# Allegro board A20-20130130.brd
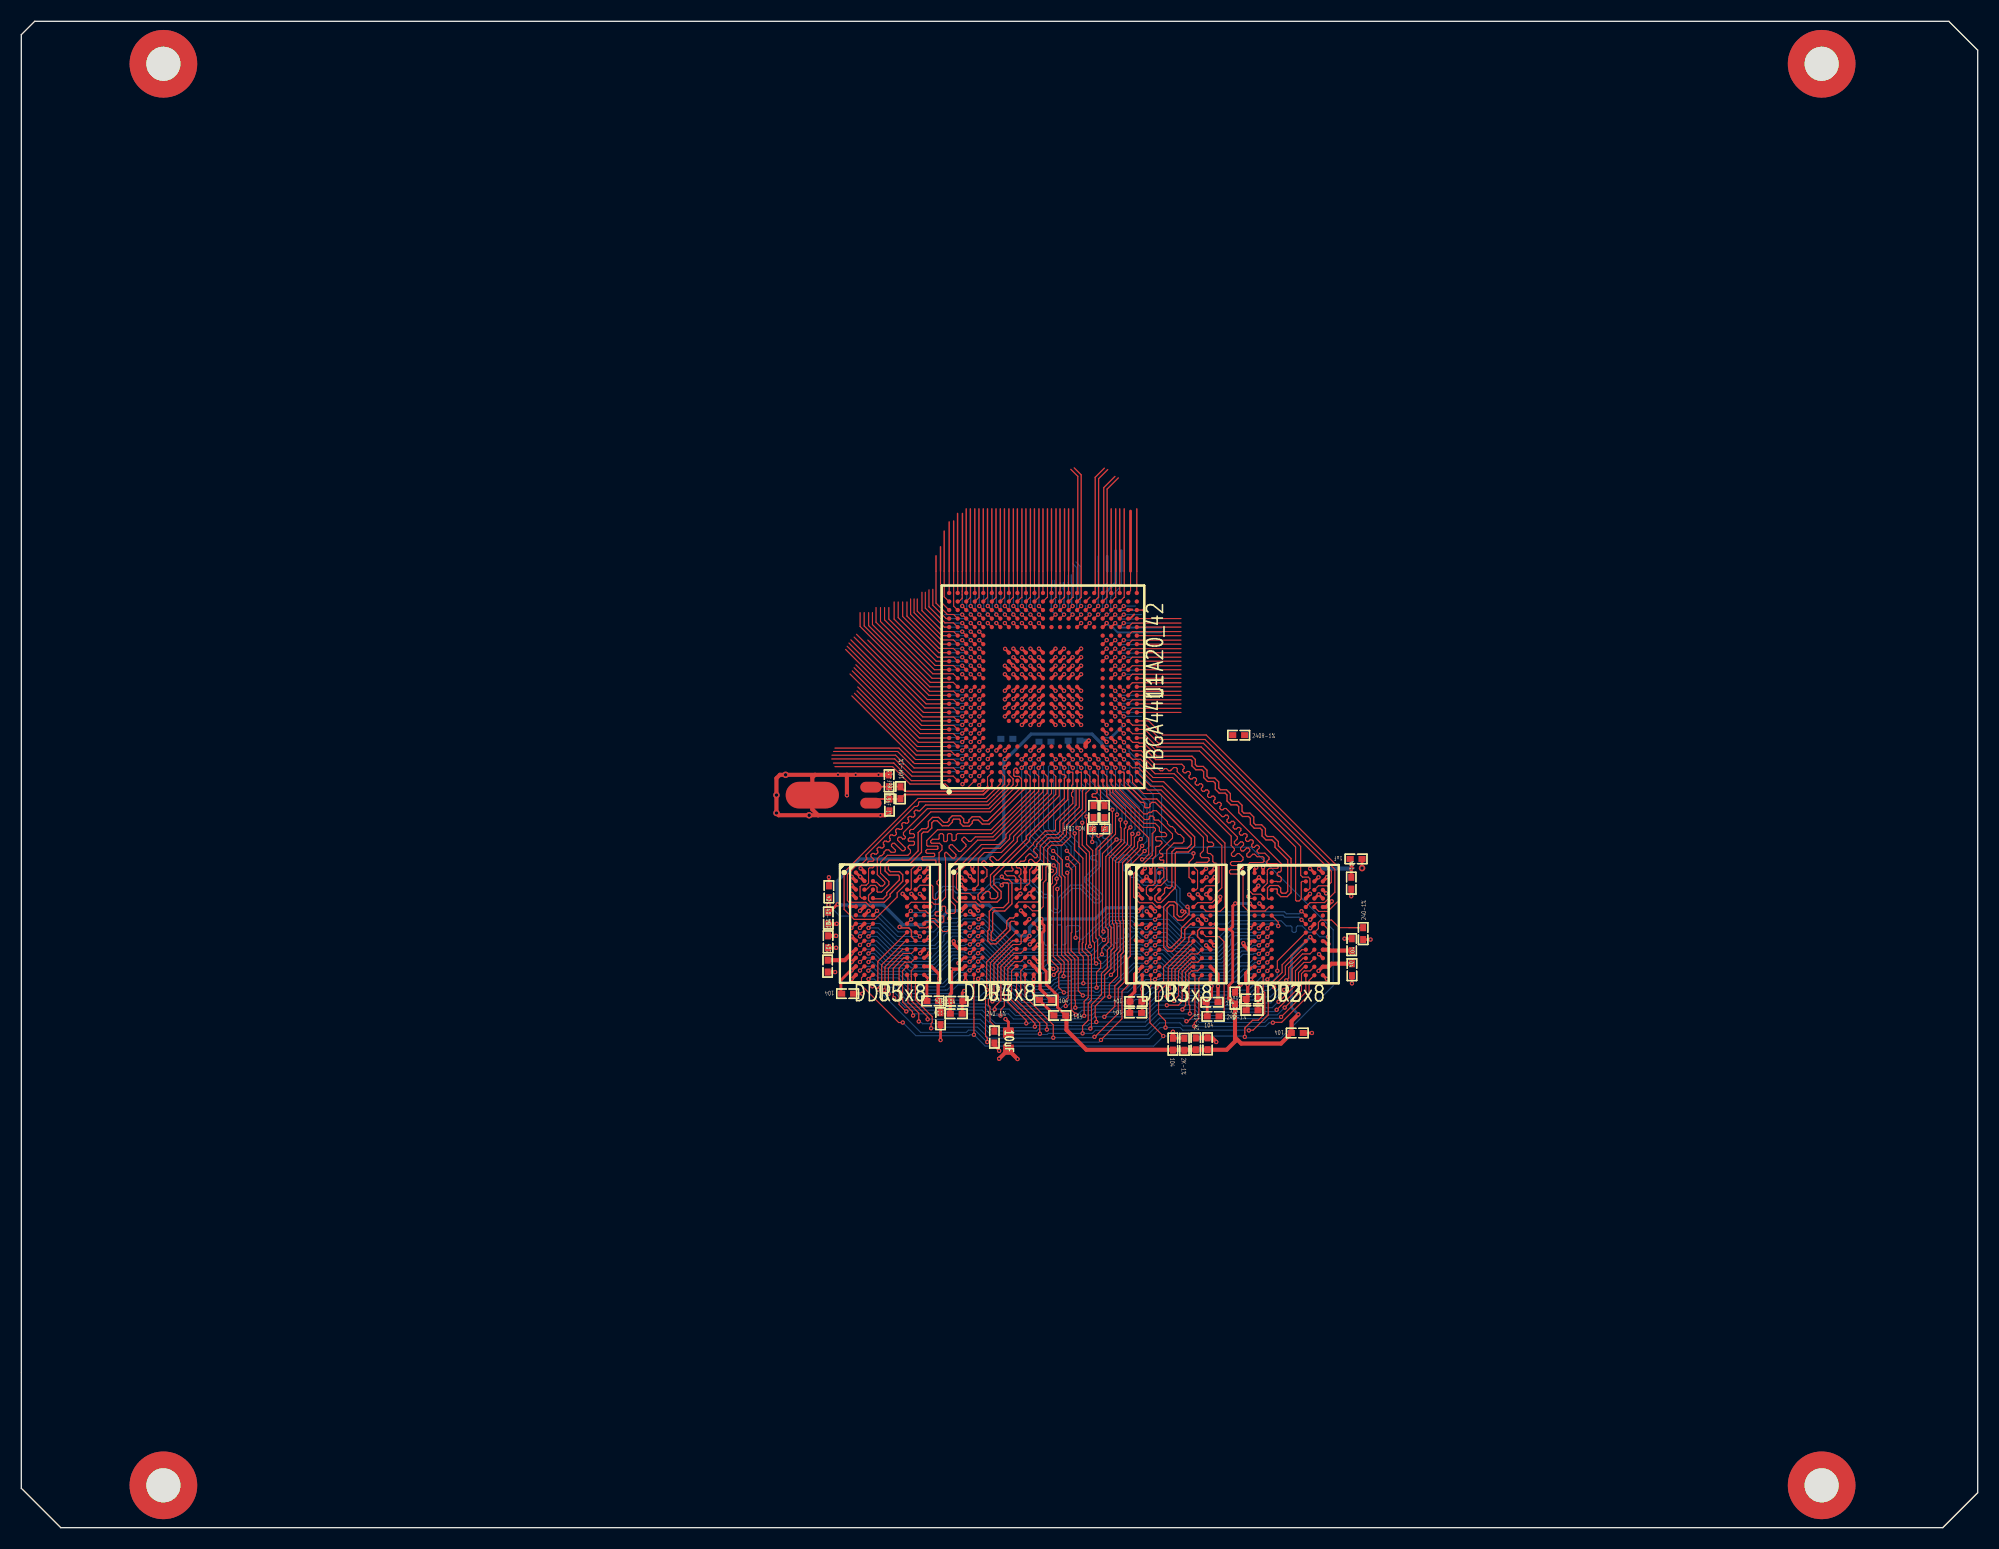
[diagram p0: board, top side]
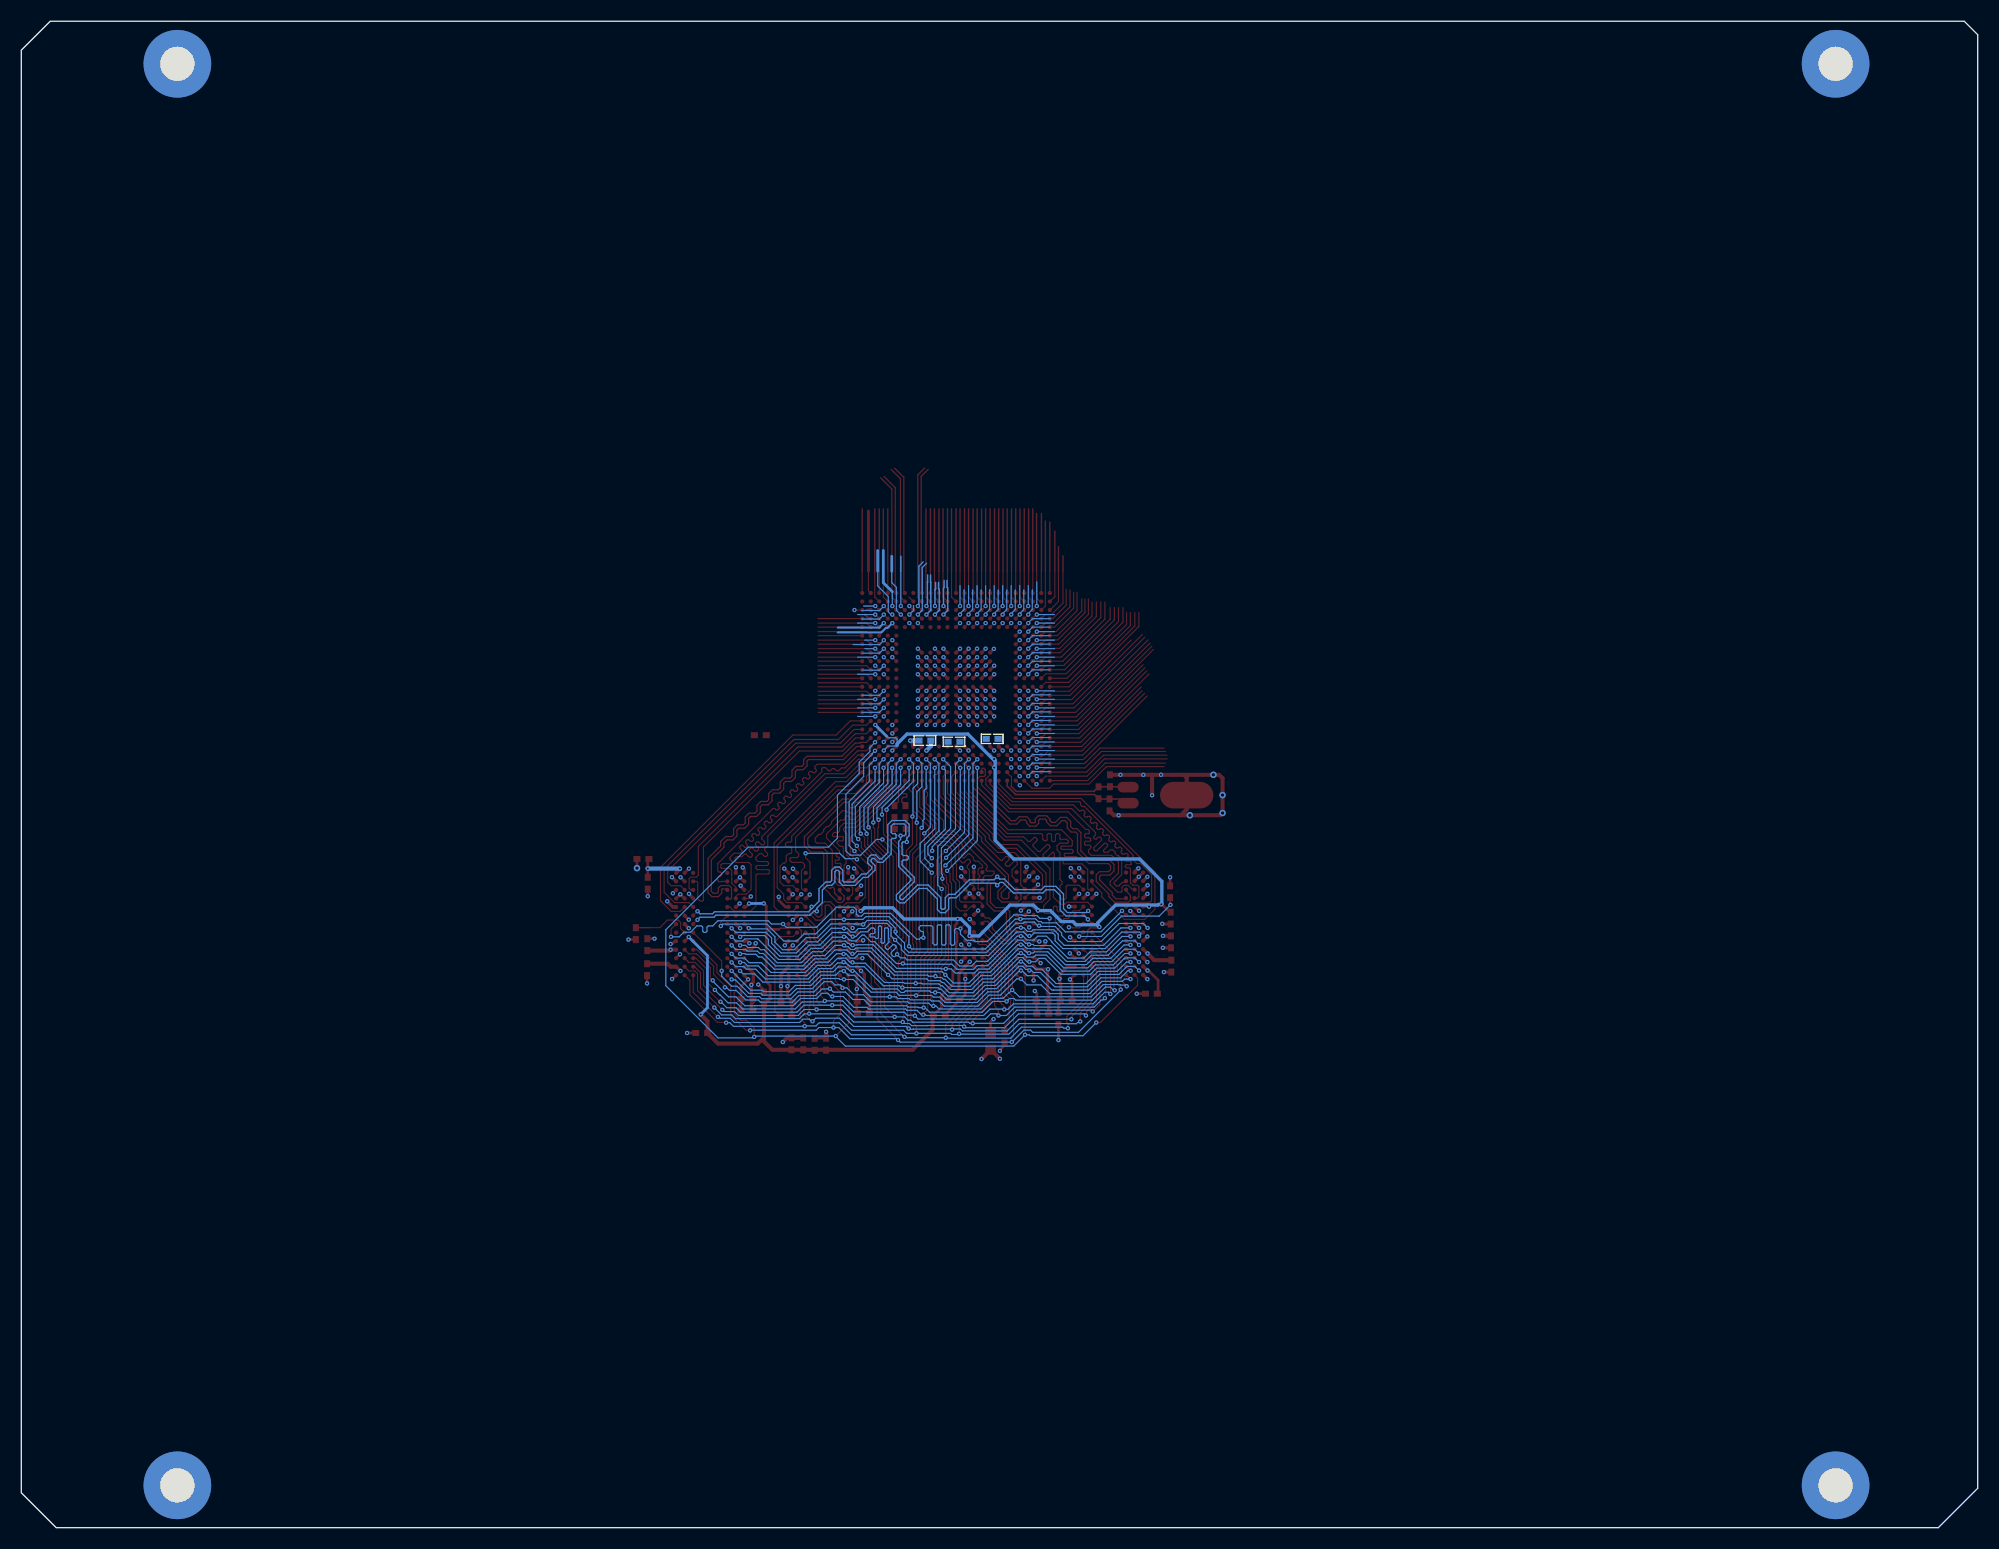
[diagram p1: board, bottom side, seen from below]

Outline 183.55 x 141.31 mm; copper layers: TOP, GND02, PWR03, BOTTOM. Coordinates in mm from the lower left corner of the outline.
Outline path: 0,140.05 1.26,141.31 180.84,141.31 183.55,138.6 183.55,3.28 180.27,0 3.7,0 0,3.7 0,140.05

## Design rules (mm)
net group ACIN-5V: nets ACIN-5V N16771897
net group ACIN-12V: nets ACIN-12V N16771865
net group AVDD10: nets AVDD10 DVDD10
net group BAT: nets BAT CHSENSE
net group BT-PCM-CLK: nets BT-PCM-CLK N23153219
net group BT-PCM-IN: nets BT-PCM-IN N23153300
net group BT-PCM-OUT: nets BT-PCM-OUT N23153273
net group BT-PCM-SYNC: nets BT-PCM-SYNC N23153244
net group BT-RST-N: nets BT-RST-N N23153193
net group CPUVDD: nets CPUVDD N23099887
net group CSI0-HSYNC: nets CSI0-HSYNC CSI0HSYNC
net group CSI0-IO-2V8: nets CSI0-IO-2V8 CSI0-VCC
net group CSI0-MCLK: nets CSI0-MCLK CSI0CK
net group CSI0-PCLK: nets CSI0-PCLK CSI0PCK
net group CSI0-VSYNC: nets CSI0-VSYNC CSI0VSYNC
net group CSI1-HSYNC: nets CSI1-HSYNC CSI1HSYNC
net group CSI1-IO-2V8: nets CSI1-IO-2V8 CSI1-VCC
net group CSI1-MCLK: nets CSI1-MCLK CSI1CK
net group CSI1-PCLK: nets CSI1-PCLK CSI1PCK
net group CSI1-VSYNC: nets CSI1-VSYNC CSI1VSYNC
net group CVBS: nets CVBS TV-CVBS
net group DP2: nets HPL HPR
net group DRAM-1V5: nets DRAM-1V5 N17835604
net group DSCK: nets DSCK SCK
net group DSCK-N: nets DSCK-N SCK-N
net group ERXCLK: nets ERXCLK RXCLK
net group ERXDV: nets ERXDV RXCTL-AD2
net group ESRXM: nets ESRXM N19311986
net group ESRXP: nets ESRXP N19311988
net group ESTXM: nets ESTXM N19311984
net group ESTXP: nets ESTXP N19311982
net group ETXD0: nets ETXD0 TXD0
net group ETXD1: nets ETXD1 TXD1
net group ETXD2: nets ETXD2 TXD2
net group ETXD3: nets ETXD3 TXD3
net group ETXEN: nets ETXEN TXCTL
net group HTX0: nets HTX0N HTX0P
net group HTX1: nets HTX1N HTX1P
net group HTX2: nets HTX2N HTX2P
net group HTXC: nets HTXCN HTXCP
net group IPSOUT: nets IPSOUT N251740
net group LCD0-PWR: nets LCD0-PWR N21047947
net group LED1-AD1: nets LED1-AD1 N22919221
net group LINEINL: nets LINEINL N16783683
net group LINEINR: nets LINEINR N16783681
net group MDI0: nets MDI0+ MDI0-
net group MDI1: nets MDI1+ MDI1-
net group MDI2: nets MDI2+ MDI2-
net group MDI3: nets MDI3+ MDI3-
net group MIC1OUT: nets MIC1OUTN MIC1OUTP
net group N16771869: nets N16771869 N16771893
net group N18122997: nets N18122997 N18122999
net group N18123031: nets N18123031 N18123039
net group N167719710: nets N167719710 N167719711
net group PI15: nets N23269636 PI15
net group QS0-CLK: nets SDQS0 SDQSB0
net group QS1-CLK: nets SDQS1 SDQSB1
net group QS2-CLK: nets SDQS2 SDQSB2
net group QS3-CLK: nets SDQS3 SDQSB3
net group RESET-N: nets N23093396 RESET-N
net group TP-S1: nets TP-S1 X1
net group TP-S2: nets TP-S2 X2
net group TP-S3: nets TP-S3 Y1
net group TP-S4: nets TP-S4 Y2
net group TP-WAKEUP: nets N23153370 TP-WAKEUP
net group UART-VCC: nets N18123022 UART-VCC
net group USB0: nets DM0 DP0
net group USB0-IDDET: nets N19190723 USB0-IDDET
net group USB1: nets DM1 DP1
net group USB2: nets DM2 DP2
net group A-GND: nets A-GND AVCC LRADC0 N2504410 N18051529 N18051532 N18051570 N18051574 N18051579 N18051588 N18051600 VRA1 VRA2 VRP
net group CLK125: nets CLK125 EGCLKIN N23153042
net group DLLVDD: nets DLLVDD ESVDD1V2 N23100083 ULVDD VDD-SYS
net group DQS0-7: nets SDQ0 SDQ1 SDQ2 SDQ3 SDQ4 SDQ5 SDQ6 SDQ7 SDQM0
net group DQS8-15: nets SDQ8 SDQ9 SDQ10 SDQ11 SDQ12 SDQ13 SDQ14 SDQ15 SDQM1
net group DQS16-23: nets SDQ16 SDQ17 SDQ18 SDQ19 SDQ20 SDQ21 SDQ22 SDQ23 SDQM2
net group DQS24-31: nets SDQ24 SDQ25 SDQ26 SDQ27 SDQ28 SDQ29 SDQ30 SDQ31 SDQM3
net group EGTXCLK: nets EGTXCLK N23153083 TXCLK
net group EMDIO: nets EMDIO EPHY-VDD25 ERXD0 ERXD1 ERXD2 ERXD3 ESVDD2V5 N23100213 RXD0-SELRGV RXD1-TXDLY RXD2-AN0 RXD3-AN1 VCC-2V5 VCC-PA VDD25-TVIN
net group ENSWREG: nets ENSWREG EPHY-AVDD33 INTB LED0-AD0 LED2-RXDLY N22919040 N22919042 N22919172 N22919199 PHYRSTB PMEB
net group EPHY-RST-N: nets EPHY-RST-N MAC-RST N23153045
net group HP-GND: nets HP-GND MICIN1 MICIN2 N19446327 N19448131 N29649340 VMIC
net group HSCL: nets HSCL HSDA N18085423 VCC-5V
net group IN0: nets IN0 N17918911 N17918913 TVIN0
net group IN1: nets IN1 N17918934 N17918936 TVIN1
net group IN2: nets IN2 N17919000 N17919002 TVIN2
net group IN3: nets IN3 N17919029 N17919031 TVIN3
net group IRQ: nets IRQ N31589329 NMI-N
net group PWM0: nets N23096818 N23096833 PWM0 VLED-
net group PWR: nets USB0-DRV USB0-VBUSDET USB1-DRV USB2-DRV USBVBUS UVCC VCC33-TVIN VCC-LCD VLED+
net group USB-ICTRL: nets N23265970 N23267698 N23268906 USB-ICTRL

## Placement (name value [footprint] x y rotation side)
C1  104  [C0402]  111.29 45.39 90 top
C2  104  [C0402]  108.04 45.35 270 top
C3  NC-10pF  [C0402]  101.08 65.54 180 top
C4  1uF  [C0402]  115.47 49.59 180 top
C5  104  [C0402]  111.71 49.29 0 top
C6  104  [C0402]  124.82 54.69 270 top
C7  104  [C0402]  124.84 52.34 90 top
C8  1uF  [C0402]  115.47 48.52 180 top
C9  104  [C0402]  124.77 60.45 90 top
C10  104  [C0402]  104.55 48.28 180 top
C11  104  [C0402]  104.57 49.35 180 top
C12  1uF  [C0402]  125.23 62.73 180 top
C13  104  [C0402]  87.78 49.39 180 top
C14  104  [C0402]  85.52 49.41 0 top
C15  104  [C0402]  96.08 49.48 0 top
C16  1uF  [C0402]  86.24 47.75 90 top
C17  104  [C0402]  75.65 52.67 90 top
C18  104  [C0402]  75.69 54.96 90 top
C19  104  [C0402]  87.71 48.21 180 top
C20  10uF  [CC0603]  92.61 45.64 270 top
C21  1uF  [C0402]  98.77 73.83 180 bottom
C22  104  [C0402]  92.46 74 180 bottom
C23  104  [C0402]  77.52 50.09 180 top
C24  104  [C0402]  96.04 73.72 0 bottom
C25  104  [C0402]  75.71 57.18 90 top
C26  104  [C0402]  97.43 48.04 0 top
C27  104  [C0402]  119.71 46.4 180 top
C28  104  [C0402]  113.87 49.67 270 top
C77  18pF-1%  [C0402]  81.45 67.8 90 top
C85  18pF-1%  [C0402]  81.41 70.06 270 top
NOREF  -  [unnamed]  168.9 137.32 0 top
NOREF#2  -  [unnamed]  13.33 3.97 0 top
NOREF#3  -  [unnamed]  13.33 137.32 0 top
NOREF#4  -  [unnamed]  168.9 3.97 0 top
R1  240R-1%  [R0402]  114.21 74.34 0 top
R2  2K-1%  [R0402]  110.19 45.38 90 top
R3  2K-1%  [R0402]  109.12 45.34 270 top
R4  240-1%  [R0402]  125.89 55.73 90 top
R5  240-1%  [R0402]  111.82 47.96 0 top
R6  240-1%  [R0402]  91.29 46.02 90 top
R7  240-1%  [R0402]  75.77 59.65 270 top
R8  24R  [R0402]  100.59 67.18 270 top
R9  24R  [R0402]  101.62 67.17 270 top
R38  10M-1%  [R0402]  82.48 68.94 90 top
U1  FBGA441-A20_42  [FBGA441C80P19X19]  95.85 78.88 90 top
U2  DDR3x8  [FBGA78P0_8B7_5X11]  118.91 56.62 0 top
U3  DDR3x8  [FBGA78P0_8B7_5X11]  108.36 56.62 0 top
U4  DDR3x8  [FBGA78P0_8B7_5X11]  91.78 56.69 0 top
U5  DDR3x8  [FBGA78P0_8B7_5X11]  81.5 56.65 0 top
X2  32768  [XCOL-SMD]  79.71 68.71 90 top

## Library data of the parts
C1 C2 C5-C7 C9-C11 C13-C15 C17-C19 C22-C28 = CAPACITOR_0: signal model: DEFAULT_CAPACITOR_1.04e+014pF_2_1
C3 C77 C85 = CAPACITOR_0
C4 C8 C12 C16 C21 = CAPACITOR_0: signal model: DEFAULT_CAPACITOR_1e+06pF_2_1
C20 = CAPACITOR_0: signal model: DEFAULT_CAPACITOR_1e+07pF_2_1
R1 R4-R7 R38 = R
R2 R3 = ?_0
R8 R9 = R1 0805: signal model: DEFAULT_RESISTOR_24OHM_2_1
U1 = FBGA441-A20_42
U2-U5 = DDR3x8-FBGA78
X2 = CRYSTAL_XCOL-3: Tolerance: RichardLC

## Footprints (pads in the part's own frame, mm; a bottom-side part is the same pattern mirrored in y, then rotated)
C0402
  rect 0.66x0.559 smd: 1(-0.559,0) 2(0.559,0)
CC0603
  rect 0.95x1.001 smd: 1(-0.8,0) 2(0.8,0)
FBGA78P0_8B7_5X11
  round 0.399 smd: A1(-3.2,4.801) A2(-2.4,4.801) A3(-1.6,4.801) A7(1.6,4.801) A8(2.4,4.801) A9(3.2,4.801) B1(-3.2,4) B2(-2.4,4) B3(-1.6,4) B7(1.6,4) B8(2.4,4) B9(3.2,4) C1(-3.2,3.2) C2(-2.4,3.2) C3(-1.6,3.2) C7(1.6,3.2) C8(2.4,3.2) C9(3.2,3.2) D1(-3.2,2.4) D2(-2.4,2.4) D3(-1.6,2.4) D7(1.6,2.4) D8(2.4,2.4) D9(3.2,2.4) E1(-3.2,1.6) E2(-2.4,1.6) E3(-1.6,1.6) E7(1.6,1.6) E8(2.4,1.6) E9(3.2,1.6) F1(-3.2,0.8) F2(-2.4,0.8) F3(-1.6,0.8) F7(1.6,0.8) F8(2.4,0.8) F9(3.2,0.8) G1(-3.2,0) G2(-2.4,0) G3(-1.6,0) G7(1.6,0) G8(2.4,0) G9(3.2,0) H1(-3.2,-0.8) H2(-2.4,-0.8) H3(-1.6,-0.8) H7(1.6,-0.8) H8(2.4,-0.8) H9(3.2,-0.8) J1(-3.2,-1.6) J2(-2.4,-1.6) J3(-1.6,-1.6) J7(1.6,-1.6) J8(2.4,-1.6) J9(3.2,-1.6) K1(-3.2,-2.4) K2(-2.4,-2.4) K3(-1.6,-2.4) K7(1.6,-2.4) K8(2.4,-2.4) K9(3.2,-2.4) L1(-3.2,-3.2) L2(-2.4,-3.2) L3(-1.6,-3.2) L7(1.6,-3.2) L8(2.4,-3.2) L9(3.2,-3.2) M1(-3.2,-4) M2(-2.4,-4) M3(-1.6,-4) M7(1.6,-4) M8(2.4,-4) M9(3.2,-4) N1(-3.2,-4.801) N2(-2.4,-4.801) N3(-1.6,-4.801) N7(1.6,-4.801) N8(2.4,-4.801) N9(3.2,-4.801)
FBGA441C80P19X19
  round 0.399 smd: A1(-8.801,8.801) A2(-8.001,8.801) A3(-7.201,8.801) A4(-6.401,8.801) A5(-5.601,8.801) A6(-4.801,8.801) A7(-4,8.801) A8(-3.2,8.801) A9(-2.4,8.801) A10(-1.6,8.801) A11(-0.8,8.801) A12(0,8.801) A13(0.8,8.801) A14(1.6,8.801) A15(2.4,8.801) A16(3.2,8.801) A17(4,8.801) A18(4.801,8.801) A19(5.601,8.801) A20(6.401,8.801) A21(7.201,8.801) A22(8.001,8.801) A23(8.801,8.801) AA1(-8.801,-7.201) AA2(-8.001,-7.201) AA3(-7.201,-7.201) AA4(-6.401,-7.201) AA5(-5.601,-7.201) AA6(-4.801,-7.201) AA7(-4,-7.201) AA8(-3.2,-7.201) AA9(-2.4,-7.201) AA10(-1.6,-7.201) AA11(-0.8,-7.201) AA12(0,-7.201) AA13(0.8,-7.201) AA14(1.6,-7.201) AA15(2.4,-7.201) AA16(3.2,-7.201) AA17(4,-7.201) AA18(4.801,-7.201) AA19(5.601,-7.201) AA20(6.401,-7.201) AA21(7.201,-7.201) AA22(8.001,-7.201) AA23(8.801,-7.201) AB1(-8.801,-8.001) AB2(-8.001,-8.001) AB3(-7.201,-8.001) AB4(-6.401,-8.001) AB5(-5.601,-8.001) AB6(-4.801,-8.001) AB7(-4,-8.001) AB8(-3.2,-8.001) AB9(-2.4,-8.001) AB10(-1.6,-8.001) AB11(-0.8,-8.001) AB12(0,-8.001) AB13(0.8,-8.001) AB14(1.6,-8.001) AB15(2.4,-8.001) AB16(3.2,-8.001) AB17(4,-8.001) AB18(4.801,-8.001) AB19(5.601,-8.001) AB20(6.401,-8.001) AB21(7.201,-8.001) AB22(8.001,-8.001) AB23(8.801,-8.001) AC1(-8.801,-8.801) AC2(-8.001,-8.801) AC3(-7.201,-8.801) AC4(-6.401,-8.801) AC5(-5.601,-8.801) AC6(-4.801,-8.801) AC7(-4,-8.801) AC8(-3.2,-8.801) AC9(-2.4,-8.801) AC10(-1.6,-8.801) AC11(-0.8,-8.801) AC12(0,-8.801) AC13(0.8,-8.801) AC14(1.6,-8.801) AC15(2.4,-8.801) AC16(3.2,-8.801) AC17(4,-8.801) AC18(4.801,-8.801) AC19(5.601,-8.801) AC20(6.401,-8.801) AC21(7.201,-8.801) AC22(8.001,-8.801) AC23(8.801,-8.801) B1(-8.801,8.001) B2(-8.001,8.001) B3(-7.201,8.001) B4(-6.401,8.001) B5(-5.601,8.001) B6(-4.801,8.001) B7(-4,8.001) B8(-3.2,8.001) B9(-2.4,8.001) B10(-1.6,8.001) B11(-0.8,8.001) B12(0,8.001) B13(0.8,8.001) B14(1.6,8.001) B15(2.4,8.001) B16(3.2,8.001) B17(4,8.001) B18(4.801,8.001) B19(5.601,8.001) B20(6.401,8.001) B21(7.201,8.001) B22(8.001,8.001) B23(8.801,8.001) C1(-8.801,7.201) C2(-8.001,7.201) C3(-7.201,7.201) C4(-6.401,7.201) C5(-5.601,7.201) C6(-4.801,7.201) C7(-4,7.201) C8(-3.2,7.201) C9(-2.4,7.201) C10(-1.6,7.201) C11(-0.8,7.201) C12(0,7.201) C13(0.8,7.201) C14(1.6,7.201) C15(2.4,7.201) C16(3.2,7.201) C17(4,7.201) C18(4.801,7.201) C19(5.601,7.201) C20(6.401,7.201) C21(7.201,7.201) C22(8.001,7.201) C23(8.801,7.201) D1(-8.801,6.401) D2(-8.001,6.401) D3(-7.201,6.401) D4(-6.401,6.401) D5(-5.601,6.401) D6(-4.801,6.401) D7(-4,6.401) D8(-3.2,6.401) D9(-2.4,6.401) D10(-1.6,6.401) D11(-0.8,6.401) D12(0,6.401) D13(0.8,6.401) D14(1.6,6.401) D15(2.4,6.401) D16(3.2,6.401) D17(4,6.401) D18(4.801,6.401) D19(5.601,6.401) D20(6.401,6.401) D21(7.201,6.401) D22(8.001,6.401) D23(8.801,6.401) E1(-8.801,5.601) E2(-8.001,5.601) E3(-7.201,5.601) E4(-6.401,5.601) E5(-5.601,5.601) E6(-4.801,5.601) E7(-4,5.601) E8(-3.2,5.601) E9(-2.4,5.601) E10(-1.6,5.601) E11(-0.8,5.601) E12(0,5.601) E13(0.8,5.601) E14(1.6,5.601) E15(2.4,5.601) E16(3.2,5.601) E17(4,5.601) E18(4.801,5.601) E19(5.601,5.601) E20(6.401,5.601) E21(7.201,5.601) E22(8.001,5.601) E23(8.801,5.601) F1(-8.801,4.801) F2(-8.001,4.801) F3(-7.201,4.801) F4(-6.401,4.801) F5(-5.601,4.801) F19(5.601,4.801) F20(6.401,4.801) F21(7.201,4.801) F22(8.001,4.801) F23(8.801,4.801) G1(-8.801,4) G2(-8.001,4) G3(-7.201,4) G4(-6.401,4) G5(-5.601,4) G19(5.601,4) G20(6.401,4) G21(7.201,4) G22(8.001,4) G23(8.801,4) H1(-8.801,3.2) H2(-8.001,3.2) H3(-7.201,3.2) H4(-6.401,3.2) H5(-5.601,3.2) H8(-3.2,3.2) H9(-2.4,3.2) H10(-1.6,3.2) H11(-0.8,3.2) H12(0,3.2) H13(0.8,3.2) H14(1.6,3.2) H15(2.4,3.2) H16(3.2,3.2) H19(5.601,3.2) H20(6.401,3.2) H21(7.201,3.2) H22(8.001,3.2) H23(8.801,3.2) J1(-8.801,2.4) J2(-8.001,2.4) J3(-7.201,2.4) J4(-6.401,2.4) J5(-5.601,2.4) J8(-3.2,2.4) J9(-2.4,2.4) J10(-1.6,2.4) J11(-0.8,2.4) J12(0,2.4) J13(0.8,2.4) J14(1.6,2.4) J15(2.4,2.4) J16(3.2,2.4) J19(5.601,2.4) J20(6.401,2.4) J21(7.201,2.4) J22(8.001,2.4) J23(8.801,2.4) K1(-8.801,1.6) K2(-8.001,1.6) K3(-7.201,1.6) K4(-6.401,1.6) K5(-5.601,1.6) K8(-3.2,1.6) K9(-2.4,1.6) K10(-1.6,1.6) K11(-0.8,1.6) K12(0,1.6) K13(0.8,1.6) K14(1.6,1.6) K15(2.4,1.6) K16(3.2,1.6) K19(5.601,1.6) K20(6.401,1.6) K21(7.201,1.6) K22(8.001,1.6) K23(8.801,1.6) L1(-8.801,0.8) L2(-8.001,0.8) L3(-7.201,0.8) L4(-6.401,0.8) L5(-5.601,0.8) L8(-3.2,0.8) L9(-2.4,0.8) L10(-1.6,0.8) L11(-0.8,0.8) L12(0,0.8) L13(0.8,0.8) L14(1.6,0.8) L15(2.4,0.8) L16(3.2,0.8) L19(5.601,0.8) L20(6.401,0.8) L21(7.201,0.8) L22(8.001,0.8) L23(8.801,0.8) M1(-8.801,0) M2(-8.001,0) M3(-7.201,0) M4(-6.401,0) M5(-5.601,0) M8(-3.2,0) M9(-2.4,0) M10(-1.6,0) M11(-0.8,0) M12(0,0) M13(0.8,0) M14(1.6,0) M15(2.4,0) M16(3.2,0) M19(5.601,0) M20(6.401,0) M21(7.201,0) M22(8.001,0) M23(8.801,0) N1(-8.801,-0.8) N2(-8.001,-0.8) N3(-7.201,-0.8) N4(-6.401,-0.8) N5(-5.601,-0.8) N8(-3.2,-0.8) N9(-2.4,-0.8) N10(-1.6,-0.8) N11(-0.8,-0.8) N12(0,-0.8) N13(0.8,-0.8) N14(1.6,-0.8) N15(2.4,-0.8) N16(3.2,-0.8) N19(5.601,-0.8) N20(6.401,-0.8) N21(7.201,-0.8) N22(8.001,-0.8) N23(8.801,-0.8) P1(-8.801,-1.6) P2(-8.001,-1.6) P3(-7.201,-1.6) P4(-6.401,-1.6) P5(-5.601,-1.6) P8(-3.2,-1.6) P9(-2.4,-1.6) P10(-1.6,-1.6) P11(-0.8,-1.6) P12(0,-1.6) P13(0.8,-1.6) P14(1.6,-1.6) P15(2.4,-1.6) P16(3.2,-1.6) P19(5.601,-1.6) P20(6.401,-1.6) P21(7.201,-1.6) P22(8.001,-1.6) P23(8.801,-1.6) R1(-8.801,-2.4) R2(-8.001,-2.4) R3(-7.201,-2.4) R4(-6.401,-2.4) R5(-5.601,-2.4) R8(-3.2,-2.4) R9(-2.4,-2.4) R10(-1.6,-2.4) R11(-0.8,-2.4) R12(0,-2.4) R13(0.8,-2.4) R14(1.6,-2.4) R15(2.4,-2.4) R16(3.2,-2.4) R19(5.601,-2.4) R20(6.401,-2.4) R21(7.201,-2.4) R22(8.001,-2.4) R23(8.801,-2.4) T1(-8.801,-3.2) T2(-8.001,-3.2) T3(-7.201,-3.2) T4(-6.401,-3.2) T5(-5.601,-3.2) T8(-3.2,-3.2) T9(-2.4,-3.2) T10(-1.6,-3.2) T11(-0.8,-3.2) T12(0,-3.2) T13(0.8,-3.2) T14(1.6,-3.2) T15(2.4,-3.2) T16(3.2,-3.2) T19(5.601,-3.2) T20(6.401,-3.2) T21(7.201,-3.2) T22(8.001,-3.2) T23(8.801,-3.2) U1(-8.801,-4) U2(-8.001,-4) U3(-7.201,-4) U4(-6.401,-4) U5(-5.601,-4) U19(5.601,-4) U20(6.401,-4) U21(7.201,-4) U22(8.001,-4) U23(8.801,-4) V1(-8.801,-4.801) V2(-8.001,-4.801) V3(-7.201,-4.801) V4(-6.401,-4.801) V5(-5.601,-4.801) V19(5.601,-4.801) V20(6.401,-4.801) V21(7.201,-4.801) V22(8.001,-4.801) V23(8.801,-4.801) W1(-8.801,-5.601) W2(-8.001,-5.601) W3(-7.201,-5.601) W4(-6.401,-5.601) W5(-5.601,-5.601) W6(-4.801,-5.601) W7(-4,-5.601) W8(-3.2,-5.601) W9(-2.4,-5.601) W10(-1.6,-5.601) W11(-0.8,-5.601) W12(0,-5.601) W13(0.8,-5.601) W14(1.6,-5.601) W15(2.4,-5.601) W16(3.2,-5.601) W17(4,-5.601) W18(4.801,-5.601) W19(5.601,-5.601) W20(6.401,-5.601) W21(7.201,-5.601) W22(8.001,-5.601) W23(8.801,-5.601) Y1(-8.801,-6.401) Y2(-8.001,-6.401) Y3(-7.201,-6.401) Y4(-6.401,-6.401) Y5(-5.601,-6.401) Y6(-4.801,-6.401) Y7(-4,-6.401) Y8(-3.2,-6.401) Y9(-2.4,-6.401) Y10(-1.6,-6.401) Y11(-0.8,-6.401) Y12(0,-6.401) Y13(0.8,-6.401) Y14(1.6,-6.401) Y15(2.4,-6.401) Y16(3.2,-6.401) Y17(4,-6.401) Y18(4.801,-6.401) Y19(5.601,-6.401) Y20(6.401,-6.401) Y21(7.201,-6.401) Y22(8.001,-6.401) Y23(8.801,-6.401)
R0402
  rect 0.66x0.559 smd: 1(-0.559,0) 2(0.559,0)
unnamed
  round 6.35 hole 3.2: (0,0)
XCOL-SMD
  oval 1.001x1.999 smd: 1(-0.749,0) 2(0.749,0)
  oval 2.499x4.999 smd: 3(0,5.499)

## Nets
AGND: C2.1 C4.1 C5.1 C6.1 C7.1 C8.1 C9.1 C10.1 C11.1 C12.1 C13.1 C14.1 C15.1 C16.1 C17.1 C18.1 C19.1 C20.1 C21.1 C22.1 C23.1 C24.1 C25.1 C26.1 C27.1 C28.1 C77.1 C85.1 R1.2 R3.1 R4.1 R5.1 R6.1 R7.1 U1.AA18(GND46) U1.G3(GND0) U1.G4(GND1) U1.H16(TEST) U1.J5(GND2) U1.J11(GND13) U1.K5(GND3) U1.K11(GND14) U1.K12(GND15) U1.K13(GND16) U1.K14(GND35) U1.L10(GND17) U1.L11(GND18) U1.L12(GND19) U1.L13(GND36) U1.L14(GND37) U1.M9(GND10) U1.M10(GND20) U1.M11(GND21) U1.M12(GND22) U1.M13(GND23) U1.M14(GND38) U1.N5(GND4) U1.N10(GND11) U1.N11(GND24) U1.N12(GND25) U1.N13(GND39) U1.N14(GND40) U1.P5(GND5) U1.P10(GND12) U1.P11(GND26) U1.P12(GND27) U1.P13(GND43) U1.P14(GND42) U1.P15(PLLGND) U1.R11(GND28) U1.R12(GND29) U1.R13(GND41) U1.R14(NC1) U1.R16(NC0) U1.T11(GND30) U1.T12(GND31) U1.U5(GND6) U1.V5(GND7) U1.V19(HPGND) U1.W9(GND32) U1.W10(GND33) U1.W11(GND34) U1.W18(GND45) U1.Y7(GND8) U1.Y8(GND9) U1.Y18(GND44) U2.A1(VSS1) U2.A8(VSS2) U2.B1(VSS3) U2.B2(VSSQ1) U2.B8(VSSQ2) U2.C9(VSSQ3) U2.D1(VSSQ4) U2.D8(VSS4) U2.D9(VSSQ5) U2.F2(VSS5) U2.F8(VSS6) U2.J1(VSS7) U2.J9(VSS8) U2.L1(VSS9) U2.L9(VSS10) U2.N1(VSS11) U2.N9(VSS12) U3.A1(VSS1) U3.A8(VSS2) U3.B1(VSS3) U3.B2(VSSQ1) U3.B8(VSSQ2) U3.C9(VSSQ3) U3.D1(VSSQ4) U3.D8(VSS4) U3.D9(VSSQ5) U3.F2(VSS5) U3.F8(VSS6) U3.J1(VSS7) U3.J9(VSS8) U3.L1(VSS9) U3.L9(VSS10) U3.N1(VSS11) U3.N9(VSS12) U4.A1(VSS1) U4.A8(VSS2) U4.B1(VSS3) U4.B2(VSSQ1) U4.B8(VSSQ2) U4.C9(VSSQ3) U4.D1(VSSQ4) U4.D8(VSS4) U4.D9(VSSQ5) U4.F2(VSS5) U4.F8(VSS6) U4.J1(VSS7) U4.J9(VSS8) U4.L1(VSS9) U4.L9(VSS10) U4.N1(VSS11) U4.N9(VSS12) U5.A1(VSS1) U5.A8(VSS2) U5.B1(VSS3) U5.B2(VSSQ1) U5.B8(VSSQ2) U5.C9(VSSQ3) U5.D1(VSSQ4) U5.D8(VSS4) U5.D9(VSSQ5) U5.F2(VSS5) U5.F8(VSS6) U5.J1(VSS7) U5.J9(VSS8) U5.L1(VSS9) U5.L9(VSS10) U5.N1(VSS11) U5.N9(VSS12) X2.3(SHIELD)
AVCC: U1.T19(AVCC)
VCC33-TVIN: U1.W16(VCC33-TVIN)
VCC-PA: U1.H10(VCC0-PA) U1.J10(VCC1-PA)
VDD25-TVIN: U1.W17(VDD25-TVIN)
VDD-SYS: U1.J15(VDD0-SYS) U1.J16(VDD1-SYS) U1.K9(VDD2-SYS) U1.K10(VDD3-SYS) U1.K15(VDD4-SYS) U1.L8(VDD5-SYS) U1.L9(VDD6-SYS) U1.R9(VDD7-SYS) U1.R10(VDD8-SYS) U1.T8(VDD9-SYS)
A-GND: U1.U19(AGND)
BT-GPIO0: U1.E14(HSCL/UART7_TX/PS2_SCK0/PI20)
BT-GPIO1: U1.E13(HSDA/UART7_RX/PS2_SDA0/PI21)
BT-PCM-CLK: U1.A12(I2S_BCLK/AC97_BCLK/PB6)
BT-PCM-IN: U1.C9(I2S_DI/AC97_DI/SPDIF_DI/PB12)
BT-PCM-OUT: U1.A11(I2S_DO0/AC97_DO/PB8)
BT-PCM-SYNC: U1.B12(I2S_LRCK/AC97_SYNC/PB7)
BT-RST-N: U1.B13(I2S_MCLK/AC97_MCLK/PB5)
BT-UART-CTS: U1.E16(EINT29/SPI1_CLK/UART2_CTS/PI17)
BT-UART-RTS: U1.E17(EINT28/SPI1_CS0/UART2_RTS/PI16)
BT-UART-RX: U1.D14(EINT31/SPI1_MISO/UART2_RX/PI19)
BT-UART-TX: U1.E15(EINT30/SPI1_MOSI/UART2_TX/PI18)
CLK32K-IN: C77.2 R38.1 U1.F1(X32KI) X2.1
CLK32K-OUT: C85.2 R38.2 U1.F2(X32KO) X2.2
CP-INT: U1.D16(SPI0_MISO/UART6_RX/CLK_OUT_B/EI)
CP-RST-N: U1.B14(IR0_TX/SPDIF_MCLK/STANBYWFI/PB3)
CPU-REF: C1.1 C2.2 C25.2 C26.2 C27.2 C28.2 R2.1 R3.2 U1.AA8(SVREF3) U1.H3(SVREF0) U1.H4(SVREF1) U1.Y5(SVREF2) U2.E1(VREFDQ) U2.J8(VREFCA) U3.E1(VREFDQ) U3.J8(VREFCA) U4.E1(VREFDQ) U4.J8(VREFCA) U5.E1(VREFDQ) U5.J8(VREFCA)
CPUVDD: U1.H11(VDD0-CPU) U1.H12(VDD1-CPU) U1.H13(VDD2-CPU) U1.H14(VDD3-CPU) U1.J12(VDD4-CPU) U1.J13(VDD5-CPU)
CSI0-D0: U1.C23(TS0_D0/CSI0_D0/PE4)
CSI0-D1: U1.C22(TS0_D1/CSI0_D1/PE5)
CSI0-D2: U1.B23(TS0_D2/CSI0_D2/PE6)
CSI0-D3: U1.B22(TS0_D3/CSI0_D3/PE7)
CSI0-D4: U1.A23(TS0_D4/CSI0_D4/PE8)
CSI0-D5: U1.A22(TS0_D5/CSI0_D5/PE9)
CSI0-D6: U1.B21(TS0_D6/CSI0_D6/PE10)
CSI0-D7: U1.A21(TS0_D7/CSI0_D7/PE11)
CSI0-HSYNC: U1.D23(TS0_SYNC/CSI0_HSYNC/PE2)
CSI0-MCLK: U1.E22(TS0_ERR/CSI0_MCLK/PE1)
CSI0-PCLK: U1.E23(TS0_CLK/CSI0_PCLK/PE0)
CSI0-PWR: U1.B1(LCD1_D16/ETXD1/KP_IN6/SMC_DET/E)
CSI0-RST-N: U1.A2(LCD1_D13/PS2_SDA1/SMC_RST/EINT1)
CSI0-VCC: U1.F19(VCC-PE)
CSI0-VSYNC: U1.D22(TS0_DVLD/CSI0_VSYNC/PE3)
CSI1-D0: U1.D20(TS1_D0/CSI1_D0/SDC1_D2/CSI0_D8/)
CSI1-D1: U1.C21(TS1_D1/CSI1_D1/SDC1_D3/CSI0_D9/)
CSI1-D2: U1.E19(TS1_D2/CSI1_D2/UART3_TX/CSI0_D1)
CSI1-D3: U1.C20(TS1_D3/CSI1_D3/UART3_RX/CSI0_D1)
CSI1-D4: U1.D19(TS1_D4/CSI1_D4/UART3_RTS/CSI0_D)
CSI1-D5: U1.C19(TS1_D5/CSI1_D5/UART3_CTS/CSI0_D)
CSI1-D6: U1.D18(TS1_D6/CSI1_D6/UART4_TX/CSI0_D1)
CSI1-D7: U1.C18(TS1_D7/CSI1_D7/UART4_RX/CSI0_D1)
CSI1-HSYNC: U1.E20(TS1_SYNC/CSI1_HSYNC/SDC1_D0/PG2)
CSI1-MCLK: U1.E21(TS1_ERR/CSI1_MLCK/SDC1_CLK/PG1)
CSI1-PCLK: U1.F20(TS1_CLK/CSI1_PCLK/SDC1_CMD/PG0)
CSI1-PWR: U1.C1(LCD1_D17/ETXD0/KP_IN7/SMC_VCCEN)
CSI1-RST-N: U1.B2(LCD1_D14/ETXD3/KP_IN4/SMC_VPPEN)
CSI1-VCC: U1.E18(VCC-PG)
CSI1-VSYNC: U1.D21(TS1_DVLD/CSI1_VSYNC/SDC1_D1/PG3)
CVBS: U1.AB17(TVOUT3)
DLLVDD: U1.M8(VDD0-DLL) U1.N9(VDD1-DLL) U1.P9(VDD2-DLL)
DM0: U1.N20(DM0)
DM1: U1.P20(DM1)
DM2: U1.R20(DM2)
DP0: U1.N21(DP0)
DP1: U1.P21(DP1)
DP2: U1.R21(DP2)
DRAM-VCC: C1.2 C4.2 C5.2 C6.2 C7.2 C8.2 C9.2 C10.2 C11.2 C12.2 C13.2 C14.2 C15.2 C16.2 C17.2 C18.2 C19.2 C20.2 C21.2 C22.2 C23.2 C24.2 R2.2 U1.G5(VCC0-DRAM) U1.H5(VCC1-DRAM) U1.L5(VCC2-DRAM) U1.M5(VCC3-DRAM) U1.R5(VCC4-DRAM) U1.T5(VCC5-DRAM) U1.W5(VCC6-DRAM) U1.W6(VCC7-DRAM) U1.W7(VCC8-DRAM) U1.Y6(VCC9-DRAM) U2.A2(VDD1) U2.A9(VDD2) U2.B9(VDDQ1) U2.C1(VDDQ2) U2.D7(VDD3) U2.E2(VDDQ3) U2.E9(VDDQ4) U2.G2(VDD4) U2.G8(VDD5) U2.K1(VDD6) U2.K9(VDD7) U2.M1(VDD8) U2.M9(VDD9) U3.A2(VDD1) U3.A9(VDD2) U3.B9(VDDQ1) U3.C1(VDDQ2) U3.D7(VDD3) U3.E2(VDDQ3) U3.E9(VDDQ4) U3.G2(VDD4) U3.G8(VDD5) U3.K1(VDD6) U3.K9(VDD7) U3.M1(VDD8) U3.M9(VDD9) U4.A2(VDD1) U4.A9(VDD2) U4.B9(VDDQ1) U4.C1(VDDQ2) U4.D7(VDD3) U4.E2(VDDQ3) U4.E9(VDDQ4) U4.G2(VDD4) U4.G8(VDD5) U4.K1(VDD6) U4.K9(VDD7) U4.M1(VDD8) U4.M9(VDD9) U5.A2(VDD1) U5.A9(VDD2) U5.B9(VDDQ1) U5.C1(VDDQ2) U5.D7(VDD3) U5.E2(VDDQ3) U5.E9(VDDQ4) U5.G2(VDD4) U5.G8(VDD5) U5.K1(VDD6) U5.K9(VDD7) U5.M1(VDD8) U5.M9(VDD9)
DSCK: C3.2 R8.2 U2.F7(CK) U3.F7(CK) U4.F7(CK) U5.F7(CK)
DSCK-N: C3.1 R9.2 U2.G7(\\C\K) U3.G7(\\C\K) U4.G7(\\C\K) U5.G7(\\C\K)
EFUSE-VDDQ: U1.T9(VDDQE)
EGCLKIN: U1.D13(ECOL/GCLKIN/CAN_TX/UART1_DCD/I2)
EGTXCLK: U1.E12(ECRS/GTXCK/UART7_RX/UART1_DSR/I)
EMDC: U1.E10(MDC/UART1_RX/PA11)
EMDIO: U1.D11(MDIO/UART6_TX/UART1_RTS/PA12)
EPHY-RST-N: U1.C13(ETXERR/CAN_RX/UART1_RING/I2S1_D)
ERXCLK: U1.D9(RXCK/SPI3_MISO/PA8)
ERXD0: U1.E6(RXD0/SPI1_MISO/UART2_RX/PA3)
ERXD1: U1.D6(RXD1/SPI1_MOSI/UART2_TX/PA2)
ERXD2: U1.E5(RXD2/SPI1_CLK/UART2_CTS/PA1)
ERXD3: U1.D5(RXD3/SPI1_CS0/UART2_RTS/PA0)
ERXDV: U1.D10(ERXDV/GRXCTL/UART1_TX/PA10)
ESREXT: U1.V21(REXT_SATA)
ESRXM: U1.U20(RXM_SATA)
ESRXP: U1.U21(RXP_SATA)
ESTXM: U1.T21(TXM_SATA)
ESTXP: U1.T20(TXP_SATA)
ESVDD1V2: U1.M15(VDD12-0-SATA) U1.M16(VDD12-1-SATA)
ESVDD2V5: U1.N15(VDD25-0-SATA) U1.N16(VDD25-1-SATA)
ETXD0: U1.E8(TXD0/SPI3_MOSI/PA7)
ETXD1: U1.D8(TXD1/SPI3_CLK/PA6)
ETXD2: U1.E7(TXD2/SPI3_CS0/PA5)
ETXD3: U1.D7(TXD3/SPI1_CS1/PA4)
ETXEN: U1.E11(ETXEN/GTXCTL/UART6_RX/UART1_CTS)
FMINL: U1.Y20(FMINL)
FMINR: U1.Y21(FMINR)
GS-INT1: U1.A6(LCD1_D0/UART3_TX/EINT0/CSI1_D0/)
GY-INT1: U1.C2(LCD1_D18/ERXCK/KP_OUT0/SMC_SLK/)
GY-INT2: U1.D1(LCD1_D19/ERXERR/KP_OUT1/SMC_SDA)
HCEC: U1.P23(CEC_HDMI)
HHPD: U1.P22(HPD_HDMI)
HPBP: U1.AC19(HPBP)
HPCOM: U1.AA19(HPCOM) U1.AA20(HPCOMFB)
HPL: U1.Y19(HPOUTL)
HPR: U1.W19(HPOUTR)
HPVCC: U1.AB19(VCC-HP) U1.H8(VCC0) U1.H9(VCC1) U1.H15(VCC2) U1.J8(VCC3) U1.J9(VCC4) U1.J14(VCC5) U1.N19(VCC-PF) U1.W12(VCC0-LVDS) U1.W13(VCC1-LVDS) U1.W14(VCC2-LVDS)
HSCL: U1.R23(SCL_HDMI)
HSDA: U1.R22(SDA_HDMI)
HTX0N: U1.V22(TX0N_HDMI)
HTX0P: U1.V23(TX0P_HDMI)
HTX1N: U1.U22(TX1N_HDMI)
HTX1P: U1.U23(TX1P_HDMI)
HTX2N: U1.T22(TX2N_HDMI)
HTX2P: U1.T23(TX2P_HDMI)
HTXCN: U1.W22(TXCN_HDMI)
HTXCP: U1.W23(TXCP_HDMI)
HVP: U1.T13(VCC-HDMI)
HVREGIO1: U1.T14(VREG1_HDMI)
I2S1-BCLK: U1.D12(ETXCK/UART7_TX/UART1_DTR/I2S1_B)
I2S1-MCLK: U1.E9(ERXERR/SPI3_CS1/I2S1_MCLK/PA9)
IR-RX: U1.A13(IR0_RX/PB4)
JTAG-CK: U1.B10(JTAG_CK0/SPI2_CLK/PB15)
JTAG-DI: U1.B9(JTAG_DI0/SPI2_MISO/PB17)
JTAG-DO: U1.A9(JTAG_DO0/SPI2_MOSI/PB16)
JTAG-MS: U1.A10(JTAG_MS0/SPI2_CS0/PB14)
JTAG-SEL: U1.T10(JTAG_SEL)
LCD0-BL-EN: U1.B4(LCD1_D7/UART5_RX/MS_CLK/EINT7/C)
LCD0-CLK: U1.Y9(LCD0_CLK/SMC_VCCEN/PD24)
LCD0-D0: U1.AB15(LCD0_D0/LVDS0_VP0/PD0)
LCD0-D1: U1.AC15(LCD0_D1/LVDS0_VN0/PD1)
LCD0-D2: U1.AB14(LCD0_D2/LVDS0_VP1/PD2)
LCD0-D3: U1.AC14(LCD0_D3/LVDS0_VN1/PD3)
LCD0-D4: U1.AB13(LCD0_D4/LVDS0_VP2/PD4)
LCD0-D5: U1.AC13(LCD0_D5/LVDS0_VN2/PD5)
LCD0-D6: U1.AB12(LCD0_D6/LVDS0_VPC/PD6)
LCD0-D7: U1.AC12(LCD0_D7/LVDS0_VNC/PD7)
LCD0-D8: U1.AB11(LCD0_D8/LVDS0_VP3/PD8)
LCD0-D9: U1.AC11(LCD0_D9/LVDS0_VN3/PD9)
LCD0-D10: U1.Y15(LCD0_D10/LVDS1_VP0/PD10)
LCD0-D11: U1.AA15(LCD0_D11/LVDS1_VN0/PD11)
LCD0-D12: U1.Y14(LCD0_D12/LVDS1_VP1/PD12)
LCD0-D13: U1.AA14(LCD0_D13/LVDS1_VN1/PD13)
LCD0-D14: U1.Y13(LCD0_D14/LVDS1_VP2/PD14)
LCD0-D15: U1.AA13(LCD0_D15/LVDS1_VN2/PD15)
LCD0-D16: U1.Y12(LCD0_D16/LVDS1_VPC/PD16)
LCD0-D17: U1.AA12(LCD0_D17/LVDS1_VNC/PD17)
LCD0-D18: U1.Y11(LCD0_D18/LVDS1_VP3/PD18)
LCD0-D19: U1.AA11(LCD0_D19/LVDS1_VN3/PD19)
LCD0-D20: U1.Y10(LCD0_D20/CSI1_MCLK/PD20)
LCD0-D21: U1.AA10(LCD0_D21/SMC_VPPEN/PD21)
LCD0-D22: U1.AB10(LCD0_D22/SMC_VPPPP/PD22)
LCD0-D23: U1.AC10(LCD0_D23/SMC_DET/PD23)
LCD0-DE: U1.AA9(LCD0_DE/SMC_RST/PD25)
LCD0-HSYNC: U1.AB9(LCD0_HSYNC/SMC_SLK/PD26)
LCD0-PWR: U1.C4(LCD1_D8/ERXD3/KP_IN0/MS_D0/EINT)
LCD0-SCK: U1.C11(I2S_DO2/PB10)
LCD0-SDA: U1.C10(I2S_DO3/PB11)
LCD0-VSYNC: U1.AC9(LCD0_VSYNC/SMC_SDA/PD27)
LINEINL: U1.AB20(LINEINL)
LINEINR: U1.AB21(LINEINR)
LRADC0: U1.AB23(LRADC0)
LRADC1: U1.AB22(LRADC1)
LS-INT: U1.D2(LCD1_D20/ERXDV/CAN_TX/EINT20/CS)
MIC1OUTN: U1.AC23(PHOUTN)
MIC1OUTP: U1.AC22(PHOUTP)
MICIN1: U1.AC20(MICIN1)
MICIN2: U1.AC21(MICIN2)
NALE: U1.M22(NALE/SPI0_MISO/PC1)
NAND-VCC: U1.H19(VCC0-PC) U1.J19(VCC1-PC)
NCE0-N: U1.K23(NCE0/PC4)
NCE1-N: U1.L22(NCE1/PC3)
NCE2-N: U1.F23(NCE2/PC17)
NCE3-N: U1.F22(NCE3/PC18)
NCLE: U1.L23(NCLE/SPI0_CLK/PC2)
ND0: U1.H23(NDQ0/SDC2_D0/PC8)
ND1: U1.H22(NDQ1/SDC2_D1/PC9)
ND2: U1.G23(NDQ2/SDC2_D2/PC10)
ND3: U1.G22(NDQ3/SDC2_D3/PC11)
ND4: U1.H21(NDQ4/PC12)
ND5: U1.H20(NDQ5/PC13)
ND6: U1.G21(NDQ6/PC14)
ND7: U1.G20(NDQ7/PC15)
NDQS: U1.F21(NDQS/PC24)
NMI-N: U1.F5(NMI#)
NRB0-N: U1.J23(NRB0/SDC2_CMD/PC6)
NRB1-N: U1.J22(NRB1/SDC2_CLK/PC7)
NRE-N: U1.K22(NRE#/PC5)
NWE-N: U1.M23(NWE#/SPI0_MOSI/PC0)
NWP: U1.M21(NWP/PC16)
OSC24MI: U1.N23(X24MI)
OSC24MO: U1.N22(X24MO)
PA-SHDN-N: U1.A1(LCD1_D15/ETXD2/KP_IN5/SMC_VPPPP)
PC19: U1.L21(NCE4/SPI2_CS0/PC19)
PC20: U1.K21(NCE5/SPI2_CLK/PC20)
PC21: U1.J21(NCE6/SPI2_MOSI/PC21)
PC22: U1.J20(NCE7/SPI2_MISO/PC22)
PI10: U1.C17(SPI0_CS0/UART5_TX/EINT22/PI10)
PI11: U1.D17(SPI0_CLK/UART5_RX/EINT23/PI11)
PI12: U1.C16(SPI0_MOSI/UART6_TX/CLK_OUT_A/EI)
PI14: U1.C15(PS2_SCK1/TCLKIN0/EINT26/SPI0_CS)
PI15: U1.D15(PS2_SDA1/TCLKIN1/EINT27/SPI1_CS)
PLLDV: U1.T16(PLLDV)
PLLVP: U1.P16(VCC-PLL)
PLLVREG: U1.R15(PLLVREG)
PWM0: U1.A14(PWM0/PB2)
RESET-N: U1.C14(RESET#)
RTCVDD: U1.K8(VDD-RTC)
SA0: U1.W4(SA0) U2.K3(A0) U3.K3(A0) U4.K3(A0) U5.K3(A0)
SA1: U1.R4(SA1) U2.L7(A1) U3.L7(A1) U4.L7(A1) U5.L7(A1)
SA2: U1.U4(SA2) U2.L3(A2) U3.L3(A2) U4.L3(A2) U5.L3(A2)
SA3: U1.M4(SA3) U2.K2(A3) U3.K2(A3) U4.K2(A3) U5.K2(A3)
SA4: U1.Y4(SA4) U2.L8(A4) U3.L8(A4) U4.L8(A4) U5.L8(A4)
SA5: U1.N4(SA5) U2.L2(A5) U3.L2(A5) U4.L2(A5) U5.L2(A5)
SA6: U1.V4(SA6) U2.M8(A6) U3.M8(A6) U4.M8(A6) U5.M8(A6)
SA7: U1.M3(SA7) U2.M2(A7) U3.M2(A7) U4.M2(A7) U5.M2(A7)
SA8: U1.AA3(SA8) U2.N8(A8) U3.N8(A8) U4.N8(A8) U5.N8(A8)
SA9: U1.P4(SA9) U2.M3(A9) U3.M3(A9) U4.M3(A9) U5.M3(A9)
SA10: U1.L3(SA10) U2.H7(A10/AP) U3.H7(A10/AP) U4.H7(A10/AP) U5.H7(A10/AP)
SA11: U1.W3(SA11) U2.M7(A11) U3.M7(A11) U4.M7(A11) U5.M7(A11)
SA12: U1.P3(SA12) U2.K7(A12/BC#) U3.K7(A12/BC#) U4.K7(A12/BC#) U5.K7(A12/BC#)
SA13: U1.Y3(SA13) U2.N3(A13) U3.N3(A13) U4.N3(A13) U5.N3(A13)
SA14: U1.R3(SA14) U2.N7(A14) U3.N7(A14) U4.N7(A14) U5.N7(A14)
SA15: U1.AA4(SA15) U2.J7(A15) U3.J7(A15) U4.J7(A15) U5.J7(A15)
SBA0: U1.K3(SBA0) U2.J2(BA0) U3.J2(BA0) U4.J2(BA0) U5.J2(BA0)
SBA1: U1.L4(SBA1) U2.K8(BA1) U3.K8(BA1) U4.K8(BA1) U5.K8(BA1)
SBA2: U1.K4(SBA2) U2.J3(BA2) U3.J3(BA2) U4.J3(BA2) U5.J3(BA2)
SCAS: U1.U3(SCAS) U2.G3(\\C\A\S) U3.G3(\\C\A\S) U4.G3(\\C\A\S) U5.G3(\\C\A\S)
SCK: R8.1 U1.V1(SCK)
SCK-N: R9.1 U1.V2(SCK#)
SCKE: U1.N3(SCKE) U2.G9(CKE) U3.G9(CKE) U4.G9(CKE) U5.G9(CKE)
SCS: U1.V3(SCS0) U2.H2(\\C\S) U3.H2(\\C\S) U4.H2(\\C\S) U5.H2(\\C\S)
SD0-CLK: U1.L20(SDC0_CLK/UART0_TX/PF2)
SD0-CMD: U1.L19(SDC0_CMD/JTAG_DO1/PF3)
SD0-D0: U1.M19(SDC0_D0/JTAG_DI1/PF1)
SD0-D1: U1.M20(SDC0_D1/JTAG_MS1/PF0)
SD0-D2: U1.K19(SDC0_D2/JTAG_CK1/PF5)
SD0-D3: U1.K20(SDC0_D3/UART0_RX/PF4)
SD0-DET-N: U1.B6(LCD1_D1/UART3_RX/EINT1/CSI1_D1/)
SD1-CLK: U1.E2(LCD1_D23/ETXEN/KP_OUT3/SDC1_CLK)
SD1-CMD: U1.E1(LCD1_D22/EMDIO/KP_OUT2/SDC1_CMD)
SD1-D0: U1.E3(LCD1_CLK/ETXCK/KP_OUT4/SDC1_D0/)
SD1-D1: U1.E4(LCD1_DE/ECRS/KP_OUT5/SDC1_D1/CS)
SD1-D2: U1.F3(LCD1_HSYNC/ECOL/KP_OUT6/SDC1_D2)
SD1-D3: U1.F4(LCD1_VSYNC/ETXERR/KP_OUT7/SDC1_)
SD1-DET-N: U1.C6(LCD1_D2/UART3_RTS/EINT2/CSI1_D2)
SD3-CLK: U1.B18(SDC3_CLK/PI5)
SD3-CMD: U1.A18(SDC3_CMD/PI4)
SD3-D0: U1.A17(SDC3_D0/PI6)
SD3-D1: U1.B17(SDC3_D1/PI7)
SD3-D2: U1.A16(SDC3_D2/PI8)
SD3-D3: U1.B16(SDC3_D3/PI9)
SD3-DET-N: U1.B3(LCD1_D11/ERXD0/KP_IN3/MS_D3/EIN)
SDQ0: U1.AC7(SDQ0) U2.C8(DQ3)
SDQ1: U1.AC4(SDQ1) U2.C2(DQ2)
SDQ2: U1.AC8(SDQ2) U2.E8(DQ5)
SDQ3: U1.AB5(SDQ3) U2.B3(DQ0)
SDQ4: U1.AB7(SDQ4) U2.C7(DQ1)
SDQ5: U1.AB8(SDQ5) U2.E7(DQ7)
SDQ6: U1.AB4(SDQ6) U2.D2(DQ6)
SDQ7: U1.AC3(SDQ7) U2.E3(DQ4)
SDQ8: U1.AA1(SDQ8) U3.C2(DQ2)
SDQ9: U1.AC1(SDQ9) U3.C8(DQ3)
SDQ10: U1.Y1(SDQ10) U3.D2(DQ6)
SDQ11: U1.AB2(SDQ11) U3.C7(DQ1)
SDQ12: U1.AC2(SDQ12) U3.E7(DQ7)
SDQ13: U1.W2(SDQ13) U3.E3(DQ4)
SDQ14: U1.AB3(SDQ14) U3.E8(DQ5)
SDQ15: U1.Y2(SDQ15) U3.B3(DQ0)
SDQ16: U1.T2(SDQ16) U4.C8(DQ3)
SDQ17: U1.N2(SDQ17) U4.C2(DQ2)
SDQ18: U1.U2(SDQ18) U4.E8(DQ5)
SDQ19: U1.P1(SDQ19) U4.B3(DQ0)
SDQ20: U1.T1(SDQ20) U4.C7(DQ1)
SDQ21: U1.U1(SDQ21) U4.E7(DQ7)
SDQ22: U1.N1(SDQ22) U4.D2(DQ6)
SDQ23: U1.M2(SDQ23) U4.E3(DQ4)
SDQ24: U1.J1(SDQ24) U5.C2(DQ2)
SDQ25: U1.L1(SDQ25) U5.C8(DQ3)
SDQ26: U1.H1(SDQ26) U5.D2(DQ6)
SDQ27: U1.K2(SDQ27) U5.C7(DQ1)
SDQ28: U1.L2(SDQ28) U5.E7(DQ7)
SDQ29: U1.G2(SDQ29) U5.E3(DQ4)
SDQ30: U1.M1(SDQ30) U5.E8(DQ5)
SDQ31: U1.H2(SDQ31) U5.B3(DQ0)
SDQM0: U1.AC6(SDQM0) U2.B7(DM/TDQS)
SDQM1: U1.W1(SDQM1) U3.B7(DM/TDQS)
SDQM2: U1.R2(SDQM2) U4.B7(DM/TDQS)
SDQM3: U1.G1(SDQM3) U5.B7(DM/TDQS)
SDQS0: U1.AB6(SDQS0) U2.C3(DQS)
SDQS1: U1.AB1(SDQS1) U3.C3(DQS)
SDQS2: U1.R1(SDQS2) U4.C3(DQS)
SDQS3: U1.K1(SDQS3) U5.C3(DQS)
SDQSB0: U1.AC5(SDQS0#) U2.D3(\\D\Q\S)
SDQSB1: U1.AA2(SDQS1#) U3.D3(\\D\Q\S)
SDQSB2: U1.P2(SDQS2#) U4.D3(\\D\Q\S)
SDQSB3: U1.J2(SDQS3#) U5.D3(\\D\Q\S)
SODT: U1.AA5(ODT) U2.G1(ODT) U3.G1(ODT) U4.G1(ODT) U5.G1(ODT)
SRAS: U1.T4(SRAS) U2.F3(\\R\A\S) U3.F3(\\R\A\S) U4.F3(\\R\A\S) U5.F3(\\R\A\S)
SRST: U1.AA6(SRST) U2.N2(\\R\E\S\E\T\) U3.N2(\\R\E\S\E\T\) U4.N2(\\R\E\S\E\T\) U5.N2(\\R\E\S\E\T\)
SWE: U1.T3(SWE) U2.H3(\\W\E) U3.H3(\\W\E) U4.H3(\\W\E) U5.H3(\\W\E)
TP-INT: U1.D3(LCD1_D21/EMDC/CAN_RX/EINT21/CSI)
TP-WAKEUP: U1.B11(SPI2_CS1/SPDIF_DO/PB13)
TVDACVCC: U1.W15(VCC33-TVOUT)
TVIN0: U1.AC18(TVIN0)
TVIN1: U1.AB18(TVIN1)
TVIN2: U1.AA17(TVIN2)
TVIN3: U1.Y17(TVIN3)
TWI0-SCK: U1.A15(TWI0_SCK/PB0)
TWI0-SDA: U1.B15(TWI0_SDA/PB1)
TWI1-SCK: U1.A8(TWI1_SCK/PB18)
TWI1-SDA: U1.B8(TWI1_SDA/PB19)
TWI2-SCK: U1.C8(TWI2_SCK/PB20)
TWI2-SDA: U1.C7(TWI2_SDA/PB21)
TWI3-SCK: U1.A20(TWI3_SCK/PI0)
TWI3-SDA: U1.B20(TWI3_SDA/PI1)
TWI4-SCK: U1.A19(TWI4_SCK/PI2)
TWI4-SDA: U1.B19(PWM1/TWI4_SDA/PI3)
UART0-RX: U1.B7(UART0_RX/IR1_RX/PB23)
UART0-TX: U1.A7(UART0_TX/IR1_TX/PB22)
UBOOT: U1.W8(UBOOT_SEL)
ULVDD: U1.K16(VDD-USB)
USB0-DRV: U1.C12(I2S_DO1/PB9)
USB0-IDDET: U1.B5(LCD1_D4/UART4_TX/EINT4/CSI1_D4/)
USB0-VBUSDET: U1.C5(LCD1_D5/UART4_RX/EINT5/CSI1_D5/)
USB1-DRV: U1.A4(LCD1_D6/UART5_TX/MS_BS/EINT6/CS)
USB2-DRV: U1.A5(LCD1_D3/UART3_CTS/EINT3/CSI1_D3)
USB-ICTRL: U1.G19(SPI0_CS0/PC23)
UVCC: U1.L15(VCC1-USB) U1.L16(VCC0-USB)
VGA-B: U1.AB16(TVOUT1)
VGA-G: U1.AC16(TVOUT0)
VGA-R: U1.AC17(TVOUT2)
VMIC: U1.AA21(VMIC)
VRA1: U1.W20(VRA1)
VRA2: U1.V20(VRA2)
VRN-TVIN: U1.Y16(VRN_TVIN)
VRP: U1.W21(VRP)
VRP-TVIN: U1.AA16(VRP_TVIN)
WIFI-PWR: U1.C3(LCD1_D12/PS2_SCK1/EINT12/CSI1_D)
WIFI-SHDN-N: U1.D4(LCD1_D9/ERXD2/KP_IN1/MS_D1/EINT)
WIFI-WAKEUP: U1.A3(LCD1_D10/ERXD1/KP_IN2/MS_D2/EIN)
X1: U1.Y22(X1_TP)
X2: U1.AA22(X2_TP)
Y1: U1.Y23(Y1_TP)
Y2: U1.AA23(Y2_TP)
N22542778: R1.1 U1.AA7(SZQ)
N23015680: U1.P8(SDDBG0)
N23015683: U1.R8(SDDBG1)
N23015686: U1.N8(SADBG)
N23016061: U1.T15(PLLTEST)
N23188466: R4.2 U2.H8(ZQ)
N23197845: R5.2 U3.H8(ZQ)
N23198178: R6.2 U4.H8(ZQ)
N23198522: R7.2 U5.H8(ZQ)

Pads without a net: U1 J3 J4 P19 R19; U2 A3 A7 F1 F9 H1 H9; U3 A3 A7 F1 F9 H1 H9; U4 A3 A7 F1 F9 H1 H9; U5 A3 A7 F1 F9 H1 H9

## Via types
v1: diameter 0.406, hole 0.203, TOP to BOTTOM, 560 vias
v2: diameter 0.61, hole 0.33, TOP to BOTTOM, 5 vias

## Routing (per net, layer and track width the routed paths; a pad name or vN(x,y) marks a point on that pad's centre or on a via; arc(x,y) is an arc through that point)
AGND: length 122.7
  TOP w0.102: U4.L9 94.99,53.48 v1(95.38,53.09) ; U2.D1 115.3,59.02 v1(115.11,59.21) ; 94.98,51.88 U4.N9 ; C11.1 105.11,49.33 C10.1 ; C28.1 113.87,50.41 v1(114.41,50.95) ; v1(104.76,59.42) U3.D1
  TOP w0.254: U2.A1 115.7,61.43 115.7,61.77 v1(115.86,61.93) ; U3.D8 v1(110.37,59.41) ; U3.N1 v1(105.16,50.53) 105.16,48.34 C10.1 ; U3.B8 110.8,60.62 v1(111.19,61.01) ; U1.M13 v1(95.48,80.05) ; U4.L1 88.45,53.48 v1(87.92,52.95) ; U1.R12 v1(98.63,78.5) ; C8.1 116.02,48.52 C4.1 116.02,50.76 v1(115.35,51.43) 115.39,51.46 115.39,51.48 115.71,51.8 U2.N1 ; U1.J11 v1(93.1,77.72) ; U3.B1 105.21,60.62 105.53,60.94 105.53,61.01 105.57,61.06 v1(105.57,61.06) 105.65,60.99 105.65,60.94 U3.B2 ; v1(104.57,55.1) 104.64,55.02 U3.J1 ; C7.1 v1(124.84,51.05) ; U1.N13 v1(97.03,80.05) ; U1.N10 v1(97.03,76.9) ; U1.L10 v1(94.68,76.9) ; U3.C9 111.56,59.8 v1(111.17,59.41) U3.D9 ; v1(89.02,57.82) 89.35,57.49 U4.F2 ; U1.P14 v1(97.83,80.85) ; v1(115.24,54.82) 115.44,55.02 U2.J1 ; 105.16,53.42 v1(104.64,53.42) ; U1.N12 v1(97.03,78.5) ; U4.B2 89,61.06 v1(89,61.1) 88.62,61.49 U4.A1 ; C20.1 92.61,47.43 v1(92.33,47.71) ; v1(111.16,57.01) 111.16,57.01 110.76,57.4 U3.F8 ; U1.K11 v1(93.88,77.7) ; U3.F2 105.96,57.44 v1(105.59,57.81) ; U1.L14 v1(94.68,80.85) ; U4.B8 U4.A8 v1(94.18,61.99) ; C16.1 v1(86.24,45.74) ; v1(85.15,55.38) 84.82,55.05 U5.J9 ; U2.D8 121.33,59.02 v1(121.72,59.41) U2.D9 ; v1(111.91,54.63) 111.9,54.63 111.9,54.66 111.56,55 U3.J9 ; U5.N9 84.73,51.85 v1(85.16,51.42) 84.96,51.22 C14.1 ; U3.A1 105.16,61.59 v1(105.42,61.84) ; U2.F8 121.31,57.41 v1(120.92,57.03) ; R5.1 111.26,49.19 C5.1 111.67,49.81 v1(111.67,50.79) 111.67,50.81 111.53,50.94 111.53,51.8 U3.N9 ; U2.B8 v1(121.7,61.01) ; U1.T11 v1(99.43,77.7) ; U1.K13 v1(93.88,80.05) ; v1(85.18,53.88) 84.75,53.45 U5.L9 ; U1.M12 v1(95.48,78.5) ; v1(121.75,53.79) 122.11,53.43 U2.L9 ; U2.C9 122.11,59.81 v1(122.42,59.5) ; U5.A1 v1(78.7,61.05) ; U4.J9 94.98,55.07 v1(94.62,54.71) ; U1.P11 v1(97.83,77.7) ; 95.52,49.34 C15.1 ; C15.1 96.87,48.13 C26.1 ; C15.1 94.98,50.02 v1(94.98,51.47) ; v1(122.63,54.75) 122.5,54.75 122.23,55.02 U2.J9 ; C27.1 v1(121.08,46.4) ; C2.1 109.11,45.91 R3.1 ; v1(88.03,54.99) 88.03,54.99 88.13,55.08 U4.J1 ; U2.B1 115.73,60.62 v1(116.12,61.01) U2.B2 ; U2.N9 122.14,51.82 v1(122.49,51.46) ; U1.K12 v1(93.88,78.5) ; U4.C9 v1(94.58,59.48) 94.98,59.09 U4.D9 ; U1.L12 v1(94.68,78.5) ; U1.R13 v1(98.63,80.05) ; 113.77,50.33 114.4,50.95 v1(114.41,50.95) ; v1(92.3,82.44) 92.65,82.09 U1.H16 ; U1.M9 v1(95.48,76.1) ; U1.M11 v1(95.48,77.7) ; U1.P10 v1(97.83,76.9) ; 88.27,49.32 88.27,50.15 v1(88.46,50.34) ; 88.27,49.32 C13.1 ; 88.27,49.32 C19.1 ; U1.R11 v1(98.63,77.7) ; R4.1 v1(126.59,55.17) ; U1.R14 v1(98.63,80.85) ; U1.L13 v1(94.68,80.05) ; v1(120.91,61.82) 120.91,61.82 U2.A8 ; U4.B1 88.5,60.69 v1(88.2,60.98) ; U1.P12 v1(97.83,78.5) ; U1.L11 v1(94.68,77.7) ; U1.N11 v1(97.03,77.7) ; U4.N1 v1(88.58,51.33) ; R7.1 v1(75.77,61.01) ; U1.P13 v1(97.83,80.05) ; C9.1 v1(124.77,59.23) ; v1(91.74,44.73) 91.74,44.8 91.29,45.25 R6.1 ; U1.N14 v1(97.03,80.85) ; U1.M10 v1(95.48,76.9) ; U1.T12 v1(99.43,78.5) ; U1.P15 v1(97.83,81.65) ; C12.1 v2(125.79,61.87) ; U3.A8 v1(111.15,61.81) ; C6.1 v1(124.14,55.25) ; U1.M14 v1(95.48,80.85) ; C23.1 v1(78.9,50.09) ; U1.K14 v1(93.88,80.85)
  TOP w0.305: v1(93.78,57.88) U4.F8 ; v1(77.9,61.05) U5.B1 ; C25.1 76.48,56.62 v1(76.5,56.65) ; 105.16,59.02 v1(104.76,59.42) ; v1(77.9,53.06) U5.L1 ; v1(77.9,55.45) U5.J1 ; v1(94.58,59.48) U4.D8 ; v1(77.9,59.45) U5.D1 ; v1(88.01,59.09) U4.D1 ; 94.98,53.49 v1(95.38,53.09) ; v1(77.9,51.46) U5.N1 ; v1(78.7,61.05) U5.B2 ; v1(94.98,51.47) 94.98,51.48 94.98,51.89 ; v1(79.5,57.85) U5.F2 ; v1(84.3,59.45) U5.D9 ; v1(76.35,52.12) C17.1 ; v1(76.45,54.4) C18.1 ; v1(84.3,61.85) U5.A8 ; v1(83.5,59.45) U5.D8 ; v1(84.3,61.05) U5.B8
  TOP w0.381: U1.U5 99.85,73.54 v1(100.15,73.83) ; C85.1 v1(80.42,70.62) v1(78.28,70.62) 77.46,70.62 ; 74.76,66.83 v2(73.91,66.83) 71.06,66.83 v2(70.85,67.04) v2(70.85,68.72) 70.85,70.3 71.17,70.62 v2(71.7,70.62) 74.47,70.62 ; 74.76,66.83 v1(80.6,66.83) 81.04,66.83 C77.1 ; 74.76,66.83 74.21,67.37 X2.3 74.21,70.37 74.47,70.62 ; 77.46,70.62 v1(76.62,70.62) 74.47,70.62 ; 77.46,70.62 v1(77.46,68.7) ; C2.1 v1(108.04,46.52)
  BOTTOM w0.381: C21.1 v1(100.15,73.83)
AVCC: length 0.5
  TOP w0.102: U1.T19 v1(99.43,84.85)
VCC33-TVIN: length 0.5
  TOP w0.102: U1.W16 v1(101.83,82.45)
VCC-PA: length 1.1
  TOP w0.254: U1.J10 v1(93.08,76.9) ; U1.H10 v1(92.28,76.9)
VDD25-TVIN: length 0.5
  TOP w0.102: U1.W17 v1(101.83,83.25)
VDD-SYS: length 5.3
  TOP w0.254: U1.K9 v1(93.88,76.1) ; U1.R10 v1(98.63,76.9) ; U1.J16 v1(93.08,82.45) ; U1.R9 v1(98.63,76.1) ; U1.K15 v1(93.88,81.65) ; U1.K10 v1(93.88,76.9) ; U1.J15 v1(93.08,81.65) ; U1.L9 v1(94.68,76.1) ; U1.T8 v1(99.43,75.3) ; U1.L8 v1(94.68,75.3)
A-GND: length 0.5
  TOP w0.102: U1.U19 v1(100.23,84.85)
BT-GPIO0: length 0.5
  TOP w0.102: U1.E14 v1(89.88,80.85)
BT-GPIO1: length 0.5
  TOP w0.102: U1.E13 v1(89.88,80.05)
BT-PCM-CLK: length 11.2
  TOP w0.102: U1.A12 85.23,78.88 79.49,84.62 79.49,85.84
BT-PCM-IN: length 2.2
  TOP w0.102: U1.C9 v1(88.28,76.1)
  BOTTOM w0.102: v1(88.28,76.1) 86.62,76.1
BT-PCM-OUT: length 12.3
  TOP w0.102: U1.A11 85.16,78.08 78.69,84.54 78.69,85.84
BT-PCM-SYNC: length 11.5
  TOP w0.102: 79.85,85.84 79.85,84.72 85.28,79.29 87.43,79.29 U1.B12
BT-RST-N: length 10.8
  TOP w0.102: U1.B13 87.43,80.1 85.51,80.1 80.61,85 80.61,86.31
BT-UART-CTS: length 0.5
  TOP w0.102: U1.E16 v1(89.88,82.45)
BT-UART-RTS: length 0.5
  TOP w0.102: U1.E17 v1(89.88,83.25)
BT-UART-RX: length 2.8
  TOP w0.102: U1.D14 v1(89.08,80.85)
  BOTTOM w0.102: v1(89.08,80.85) 89.08,80.87 88.67,81.27 87.02,81.27
BT-UART-TX: length 0.5
  TOP w0.102: U1.E15 v1(89.88,81.65)
CLK32K-IN: length 12.5
  TOP w0.152: X2.1 80.1,68.35 C77.2 82.45,68.35 R38.1 82.87,68.77 90.26,68.77 91.05,69.56 U1.F1
CLK32K-OUT: length 12.9
  TOP w0.102: U1.F2 91.05,70.81 90.65,70.41 90.65,69.57 90.67,69.54
  TOP w0.152: 90.67,69.54 90.21,69.07 82.91,69.07 R38.2 82.48,69.5 C85.2 79.75,69.5 X2.2
CP-INT: length 2.8
  TOP w0.102: U1.D16 v1(89.08,82.45)
  BOTTOM w0.102: 87.02,82.87 88.67,82.87 89.08,82.47 v1(89.08,82.45)
CP-RST-N: length 9.5
  TOP w0.102: 81.39,86.31 81.39,85.23 85.74,80.88 87.45,80.88 U1.B14
CPU-REF: length 149.7
  TOP w0.102: U1.AA8 v1(103.43,75.3) ; U1.Y5 v1(102.63,72.9) ; 119.17,46.4 C27.2 ; U3.E1 105.16,58.22 104.8,57.86 ; U3.J8 110.76,55.03
  TOP w0.127: 82.48,56.26 83.26,56.26 83.51,56.02 83.51,55.45 U5.J8 ; 82.48,56.26 v1(82.4,56.35) ; 82.48,56.26 82.46,56.26 82.4,56.32 ; 112.45,56.13 112.34,56.23 110.6,56.23 110.36,55.98 110.36,55.44 110.76,55.03
  TOP w0.254: C26.2 97.22,48.81 97.22,49.9 96.45,50.68 96.44,50.68 96.15,50.97 96.15,52.17 95.84,52.49 95.84,54.87 95.76,54.94 95.76,55.79 95.95,55.98 95.95,56.49 95.77,56.68 95.77,57.03 v1(95.7,57.1) ; v1(113.89,58.55) 113.65,58.32 113.65,56.38 113.4,56.13 ; 113.4,56.13 113.65,55.87 113.65,51.22 113.29,50.86 113.29,49.67 ; 113.4,56.13 112.45,56.13 ; U2.E1 115.59,58.22 v1(115.26,58.54) ; U2.J8 121.3,55.02 120.93,55.39 v1(120.93,55.41) ; v1(94.58,55.51) 94.58,55.5 94.18,55.09 U4.J8 ; C25.2 75.81,57.74 76.54,58.47 v1(76.59,58.47) ; U5.E1 v1(77.74,58.25) ; U1.H3 v1(92.28,71.3) ; U1.H4 v1(92.28,72.1)
  TOP w0.305: v1(104.8,57.84) 104.8,57.86 105.16,58.22
  TOP w0.381: v1(119.81,48.14) 119.17,47.51 119.17,46.4 118.18,45.41 114.45,45.41 113.87,46 ; 108.08,44.83 C1.1 113.09,44.83 113.87,45.61 113.87,46 ; 108.08,44.83 C2.2 ; 108.08,44.83 99.92,44.83 98.05,46.7 98.05,47.98 C26.2 ; 113.87,46 C28.2 113.31,49.67 113.29,49.67 ; v1(88.17,57.89) 88.57,58.29 U4.E1
  BOTTOM w0.102: 102.38,74.26 102.22,74.1 101.52,74.1 101.38,73.96 101.38,73.52 ; 101.38,73.38 101.45,73.32 102.23,73.32 102.63,72.92 v1(102.63,72.9)
  BOTTOM w0.254: 102.38,74.26 102.39,74.26 v1(103.43,75.3) ; v1(115.26,58.54) 115.26,58.55 v1(113.89,58.55) ; v1(120.93,55.41) 119.17,53.66 119.17,48.78 v1(119.81,48.14)
  BOTTOM w0.305: 82.57,56.55 82.57,56.72 80.88,58.4 77.89,58.4 ; 82.57,56.55 84.57,56.55 84.88,56.86 85.97,56.86 87,57.89 v1(88.17,57.89) ; 82.57,56.55 82.54,56.52 82.54,56.49 v1(82.4,56.35) ; 92.18,71.2 92.18,71.88 ; 92.18,71.2 v1(92.28,71.3) ; 92.18,71.2 92.18,64.46 90.44,62.73 78.64,62.73 76.54,60.63 76.54,58.52 v1(76.59,58.47) 76.83,58.47 76.9,58.4 77.89,58.4 ; 92.18,71.88 94.74,74.44 100.45,74.44 101.38,73.52 101.38,73.38 ; 92.18,71.88 92.18,72 v1(92.28,72.1) ; 77.89,58.4 v1(77.74,58.25) ; v1(88.17,57.89) 88.1,57.95 ; v1(88.17,57.89) 88.17,57.98 88.59,58.4 90.79,58.4 93.68,55.51 v1(94.58,55.51) 94.58,56.3 95.38,57.1 v1(95.7,57.1) 100.74,57.1 101.8,58.15 104.43,58.15 104.75,57.84 v1(104.8,57.84)
CPUVDD: length 3.2
  TOP w0.254: U1.H14 v1(92.28,80.85) ; U1.J12 v1(93.08,78.5) ; U1.H11 v1(92.28,77.7) ; U1.H13 v1(92.28,80.05) ; U1.J13 v1(93.08,80.05) ; U1.H12 v1(92.28,78.5)
CSI0-D0: length 7.9
  TOP w0.102: 88.65,89.72 U1.C23
  TOP w0.127: 88.65,95.57 88.65,89.72
CSI0-D1: length 8.9
  TOP w0.102: U1.C22 89.04,87.27 89.04,89.72
  TOP w0.127: 89.04,89.72 89.04,95.57
CSI0-D2: length 7.5
  TOP w0.102: 87.84,89.72 87.84,89.7 87.85,89.68 U1.B23
  TOP w0.127: 87.84,89.72 87.84,95.14
CSI0-D3: length 8.5
  TOP w0.102: U1.B22 87.96,86.88 88.28,87.2 88.28,87.51 88.27,87.52 88.27,87.84 88.28,87.85 88.28,89.68 88.3,89.7 88.3,89.72
  TOP w0.127: 88.3,95.14 88.3,89.72
CSI0-D4: length 6.7
  TOP w0.102: U1.A23 87.05,89.72
  TOP w0.127: 87.05,89.72 87.05,94.34
CSI0-D5: length 6.8
  TOP w0.102: 86.58,89.72 86.58,87.33 87.03,86.88 U1.A22
  TOP w0.127: 86.58,93.48 86.58,89.72
CSI0-D6: length 8.5
  TOP w0.102: U1.B21 87.84,86.08 87.47,86.45 87.47,89.72
  TOP w0.127: 87.47,94.43 87.47,89.72
CSI0-D7: length 6.3
  TOP w0.102: 86.24,89.72 86.24,86.88 87.04,86.08 U1.A21
  TOP w0.127: 86.24,92.01 86.24,89.72
CSI0-HSYNC: length 7.9
  TOP w0.102: 89.45,89.72 U1.D23
  TOP w0.127: 89.45,95.57 89.45,89.72
CSI0-MCLK: length 8.9
  TOP w0.102: 90.65,89.72 90.65,87.27 U1.E22
  TOP w0.127: 90.65,89.72 90.65,95.57
CSI0-PCLK: length 7.9
  TOP w0.102: 90.25,89.72 U1.E23
  TOP w0.127: 90.25,95.57 90.25,89.72
CSI0-PWR: length 12.7
  TOP w0.102: 76.04,72.11 81.94,72.11 83.56,70.5 87.43,70.5 U1.B1
CSI0-RST-N: length 11.6
  TOP w0.102: U1.A2 83.61,70.88 82.02,72.46 76.06,72.46
CSI0-VCC: length 0.5
  TOP w0.102: U1.F19 v1(90.68,84.85)
CSI0-VSYNC: length 8.9
  TOP w0.102: U1.D22 89.84,87.27 89.84,89.72
  TOP w0.127: 89.84,89.72 89.84,95.57
CSI1-D0: length 3
  TOP w0.102: U1.D20 v1(89.08,85.65)
  BOTTOM w0.102: 88.68,87.96 88.69,87.94 88.69,86.12 89.08,85.74 v1(89.08,85.65)
CSI1-D1: length 2.8
  TOP w0.102: U1.C21 v1(88.28,86.45)
  BOTTOM w0.102: v1(88.28,86.45) 88.28,88.71
CSI1-D2: length 0.5
  TOP w0.102: U1.E19 v1(89.88,84.85)
CSI1-D3: length 2.2
  TOP w0.102: U1.C20 v1(88.28,85.65)
  BOTTOM w0.102: v1(88.28,85.65) 86.62,85.65
CSI1-D4: length 2.8
  TOP w0.102: U1.D19 v1(89.08,84.85)
  BOTTOM w0.102: 87.02,85.27 88.67,85.27 89.08,84.87 v1(89.08,84.85)
CSI1-D5: length 2.2
  TOP w0.102: U1.C19 v1(88.28,84.85)
  BOTTOM w0.102: v1(88.28,84.85) 86.62,84.85
CSI1-D6: length 2.8
  TOP w0.102: U1.D18 v1(89.08,84.05)
  BOTTOM w0.102: 87.02,84.47 88.67,84.47 89.08,84.07 v1(89.08,84.05)
CSI1-D7: length 2.2
  TOP w0.102: U1.C18 v1(88.28,84.05)
  BOTTOM w0.102: v1(88.28,84.05) 86.62,84.05
CSI1-HSYNC: length 3
  TOP w0.102: U1.E20 v1(89.88,85.65)
  BOTTOM w0.102: 89.48,87.96 89.49,87.94 89.49,86.12 89.88,85.74 v1(89.88,85.65)
CSI1-MCLK: length 2.4
  TOP w0.102: U1.E21 v1(89.88,86.45)
  BOTTOM w0.102: v1(89.88,86.45) 89.88,88.37
CSI1-PCLK: length 3
  TOP w0.102: U1.F20 v1(90.68,85.65)
  BOTTOM w0.102: 90.28,87.96 90.29,87.94 90.29,86.12 90.68,85.74 v1(90.68,85.65)
CSI1-PWR: length 0.5
  TOP w0.102: v1(88.3,69.74) 88.35,69.79 88.36,69.79 U1.C1
CSI1-RST-N: length 12.4
  TOP w0.102: 76.21,72.81 82.21,72.81 83.76,71.27 87.46,71.27 U1.B2
CSI1-VCC: length 0.5
  TOP w0.102: U1.E18 v1(89.88,84.05)
CSI1-VSYNC: length 2.4
  TOP w0.102: U1.D21 v1(89.08,86.45)
  BOTTOM w0.102: v1(89.08,86.45) 89.08,88.37
CVBS: length 5.1
  TOP w0.102: U1.AB17 104.23,83.26 108.8,83.26
DLLVDD: length 1.6
  TOP w0.254: U1.M8 v1(95.48,75.3) ; U1.P9 v1(97.83,76.1) ; U1.N9 v1(97.03,76.1)
DM0: length 3.9
  TOP w0.102: U1.N20 v1(97.03,85.65)
  BOTTOM w0.127: v1(97.03,85.65) 96.63,86.05 96.63,88.14 96.69,88.2 96.69,88.85
DM1: length 3.7
  TOP w0.102: U1.P20 v1(97.83,85.65)
  BOTTOM w0.127: 97.49,88.67 97.49,88.25 97.49,88.12 97.49,88.06 97.42,88 97.42,86.06 v1(97.83,85.65)
DM2: length 4.4
  TOP w0.102: U1.R20 v1(98.63,85.65)
  BOTTOM w0.127: v1(98.63,85.65) 98.22,86.06 98.22,88.68 98.24,88.7 98.24,89.37
DP0: length 3
  TOP w0.102: U1.N21 v1(97.03,86.45)
  BOTTOM w0.127: 96.97,88.85 96.97,88.2 97.03,88.14 v1(97.03,86.45)
DP1: length 2.8
  TOP w0.102: U1.P21 v1(97.83,86.45)
  BOTTOM w0.127: 97.77,88.67 97.77,88.13 97.77,88.12 97.77,88.05 97.83,87.99 v1(97.83,86.45)
DP2: length 3.5
  TOP w0.102: U1.R21 v1(98.63,86.45)
  BOTTOM w0.127: v1(98.63,86.45) 98.54,86.54 98.54,88.68 98.52,88.7 98.52,89.37
DRAM-VCC: length 95.7
  TOP w0.102: U4.G2 89.35,56.69 v1(88.98,56.31) ; 115.34,52.49 115.47,52.62 U2.M1 ; U2.G2 116.5,56.62 ; U2.M9 121.72,52.22 v1(121.7,52.22) ; U5.E9 85.26,58.25 v1(85.26,58.26) ; U3.E2 v1(106.36,57.82) ; U2.B9 122.11,60.63 ; U2.G8 121.31,56.61 121.31,56.61 ; U2.K1 115.7,54.22 ; 116.02,60.14 116.02,60.13 U2.C1 ; U4.E2 89.38,58.28 ; v1(95.37,54.69) 94.98,54.3 U4.K9 ; U5.M9 85.37,52.65 85.39,52.64 ; U5.D7 83.09,59.06 83.08,59.06 ; U3.C1 v1(104.76,60.22) ; v1(95.37,61.09) 94.98,60.7 U4.B9 ; U5.A9 84.7,61.48 ; v1(120.9,59.46) 120.51,59.07 U2.D7 ; U5.K9 84.7,54.24 v1(84.33,53.87) ; v1(94.57,53.09) 94.58,53.09 U4.M9 ; U3.A9 111.56,61.42 ; U4.M1 88.28,52.39 88.27,52.39 ; U3.B9 111.56,60.62 ; U4.A2 89.37,61.49 ; 122.18,58.22 U2.E9 ; U2.A2 116.5,61.42 ; U3.M1 105.16,52.62 ; 94.57,57.08 U4.G8 ; v1(111.16,54.62) U3.K9 ; U4.A9 94.98,61.5 ; 105.96,61.43 U3.A2 ; U5.B9 84.7,60.68 ; U3.G2 105.96,56.62
  TOP w0.114: 84.27,56.29 84.28,56.27 84.94,56.27 84.99,56.32
  TOP w0.127: U5.E2 79.08,58.25 v1(78.68,57.86) ; U5.M1 78.28,52.65 v1(77.88,52.26) ; U5.K1 78.28,54.25 v1(77.88,53.86) ; 79.05,61.51 U5.A2 ; 78.28,59.86 78.29,59.86 U5.C1 ; U5.G2 79.08,56.65 v1(78.68,56.26) ; U5.G8 84.27,56.29 ; 84.99,56.32 v1(85.26,56.32)
  TOP w0.254: U1.G5 v1(91.48,72.9) ; U4.C1 88.16,60.31 v1(88.16,60.32) ; 124.77,61.82 C9.2 ; 124.77,61.82 v1(124.77,61.82) 124.88,61.93 ; 124.77,61.82 124.77,62.62 C12.2 ; C23.2 76.89,50.16 76.89,51.36 77.8,52.26 v1(77.88,52.26) ; U1.M5 v1(95.48,72.9) ; U1.Y6 v1(102.63,73.7) ; 87.96,54.29 87.96,54.28 U4.K1 ; U1.T5 v1(99.43,72.9) ; U1.W7 v1(101.83,74.5) ; U3.E9 111.85,58.22 112.48,58.86 v1(112.48,59.17) ; U1.H5 v1(92.28,72.9) ; U1.R5 v1(98.63,72.9) ; v1(116.15,58.55) 116.48,58.22 U2.E2 ; U1.L5 v1(94.68,72.9) ; U3.G8 110.76,56.65 v1(110.38,57.04) ; U1.W6 v1(101.83,73.7) ; U1.W5 v1(101.83,72.9) ; C16.2 86.24,49.25 C14.2
  TOP w0.305: 84.68,58.26 v1(85.26,58.26) ; 84.68,54.26 84.68,54.25 84.35,53.91 84.35,53.89 84.33,53.87 v1(84.33,53.87) ; 86.02,49.47 86.02,50.99 86.12,51.08 86.12,51.47 v1(86.14,51.5) 86.14,51.53 86.12,51.55 86.12,51.91 85.39,52.64 84.7,52.64 84.68,52.66 ; 114.88,49.65 114.83,49.65 114.76,49.58 ; 114.88,49.65 114.88,49.31 115.04,49.14 115.04,48.53 ; 114.88,49.65 115.05,49.82 v1(115.05,50.91) 115.05,51.01 114.87,51.19 114.87,52.02 115.34,52.49 ; 116.5,61.42 v1(116.5,61.95) ; 112.38,49.29 C5.2 v1(112.27,50.79) 112.27,51.91 U3.M9 ; v1(105.97,61.96) 105.96,61.95 105.96,61.42 ; 105.96,56.62 105.59,56.25 v1(105.55,56.25) ; 84.7,61.48 v1(85.08,61.86) ; 111.56,60.62 v1(111.96,61.02) ; 78.28,54.26 78.28,54.26 v1(77.88,53.86) ; v1(93.74,59.47) 93.61,59.33 93.61,59.31 U4.D7 ; C19.2 87.16,50.04 87.27,50.15 87.27,52.34 v1(87.22,52.39) 88.27,52.39 88.57,52.68 88.57,52.69 ; v1(120.9,59.46) 120.9,59.42 120.51,59.02 ; v1(114.65,54.83) 114.65,54.8 114.67,54.78 114.67,54.7 114.71,54.66 114.71,54.61 115.1,54.22 115.7,54.22 ; 89.38,58.28 v1(89.77,57.89) ; 111.56,61.42 v1(111.96,61.82) ; 94.98,61.5 v1(95.37,61.89) ; v1(120.93,56.23) 121.31,56.61 121.31,56.62 ; v1(77.88,52.26) 78.28,52.66 78.28,52.66 ; v1(94.57,57.09) 94.57,57.07 94.17,56.67 ; v1(116.11,56.24) 116.12,56.24 116.5,56.62 ; C15.2 95.58,50.53 95.58,52.01 95.29,52.3 95.29,52.36 v1(94.57,53.09) ; v1(95.37,61.09) 95.37,61.08 94.97,60.69 ; 79.08,56.66 v1(78.68,56.26) ; 111.56,54.22 v1(111.16,54.62) ; 104.01,49.82 103.99,49.8 C10.2 ; 104.01,49.82 C11.2 ; 104.01,49.82 104.45,50.27 104.45,51.92 v1(104.76,52.22) 104.76,52.23 105.16,52.62 ; v1(78.74,61.85) 78.78,61.85 79.05,61.57 79.05,61.49 79.08,61.46 ; v1(121.75,61.81) 121.75,61.78 122.11,61.42 ; 78.28,59.86 v1(77.88,60.26) ; 105.16,59.82 v1(104.76,60.22) ; 94.97,54.29 v1(95.37,54.69) ; 84.7,60.68 v1(85.08,61.06) ; v1(89.23,61.99) 89.23,61.67 89.37,61.53 89.37,61.49 ; 109.96,59.02 U3.D7 109.93,59.02 v1(109.57,59.38) ; v1(87.47,55) 87.47,54.9 87.47,54.89 87.47,54.77 87.96,54.29 ; 122.11,58.22 122.18,58.22 122.18,58.22 122.41,58.22 v1(122.94,58.76) ; v1(116.06,60.22) 116.02,60.18 116.02,60.14 115.7,59.82 ; 122.11,60.63 v1(122.5,61.02) ; 115.7,52.62 115.7,52.62 ; 83.08,59.06 83.08,59.06 v1(82.68,59.46) ; 79.08,58.26 v1(78.68,57.86) ; 122.11,52.62 v1(121.7,52.22) ; 105.96,58.22 v1(106.36,57.82)
  TOP w0.381: C18.2 v1(76.44,55.51) ; 111.29,45.94 C1.2 ; 111.29,45.94 111.72,45.94 v1(112.1,45.56) ; 111.29,45.94 R2.2 ; U2.K9 v1(122.63,54.22) 122.72,54.13 C6.2 ; v1(77.88,53.86) 77.25,53.23 C17.2 ; C7.2 122.91,52.9 122.63,52.62 U2.M9 ; v1(91.73,43.99) 92.59,44.84 C20.2 92.61,44.81 v1(93.46,43.96)
  BOTTOM w0.305: v1(85.26,58.26) 85.17,58.26
  BOTTOM w0.381: v1(121.75,61.81) 121.77,61.82 v1(124.77,61.82) ; C21.2 98.21,73.32 v1(98.63,72.9)
DSCK: length 90.6
  TOP w0.114: R8.2 100.59,66.07 100.52,66 C3.2 100.52,64.75 100.47,64.7 v1(100.47,64.32) ; v1(91.98,61.07) 92.24,60.81 92.64,60.81 92.94,60.51 92.94,58.52 92.27,57.85 91.29,57.85 91.13,57.68 91.13,55.99 90.99,55.85 90.99,55.18 91.09,55.08 91.33,55.08 92.44,56.19 92.44,56.89 92.74,57.19 93.09,57.19 U4.F7 ; v1(109.4,58.24) 109.56,58.09 109.56,57.56 108.98,56.98 108.51,56.98 108.13,57.37 108.13,58.33 108.06,58.39 107.77,58.39 107.49,58.12 107.49,54.58 107.68,54.39 107.87,54.39 108.84,55.36 108.84,56.23 109.96,57.35 U3.F7 ; v1(83.45,57.85) 83.1,57.51 U5.F7 ; U2.F7 120.11,57.82 v1(120.1,57.82)
  BOTTOM w0.114: v1(83.45,57.85) 83.5,57.81 83.52,57.81 83.63,57.7 85.4,57.7 85.77,58.07 85.77,59.44 86.48,60.15 87.54,60.15 87.83,59.86 90.34,59.86 91.32,60.84 91.76,60.84 v1(91.98,61.07) 92.28,60.77 94.6,60.77 95.97,59.41 96.55,59.41 96.86,59.1 96.86,58.15 97,58.01 97.18,58.01 97.28,58.11 97.28,59.1 98.46,60.28 99.47,60.28 100.82,58.93 101,58.93 101.13,59.06 101.13,59.22 99.77,60.58 99.77,61.01 100.91,62.15 100.91,62.51 100.79,62.63 100.46,62.63 100.33,62.76 100.33,62.93 100.45,63.05 100.79,63.05 100.91,63.17 100.91,64.24 100.83,64.32 v1(100.47,64.32) 100.47,64.68 100.25,64.91 100.25,65.98 100.6,66.33 101.86,66.33 102.25,65.94 102.25,63.33 102.85,62.73 103.02,62.73 103.39,63.1 103.82,63.1 104.13,62.78 104.13,62.35 103.77,61.98 103.77,61.82 104.27,61.32 104.69,61.32 105.44,60.56 106.35,60.56 106.48,60.69 106.48,61.67 106.78,61.97 107.22,61.97 107.53,61.66 107.53,60.69 107.65,60.56 108.08,60.56 108.71,59.94 108.71,58.77 109.23,58.24 v1(109.4,58.24) 109.4,58.06 109.69,57.77 118.51,57.77 118.7,57.58 119.86,57.58 v1(120.1,57.82)
